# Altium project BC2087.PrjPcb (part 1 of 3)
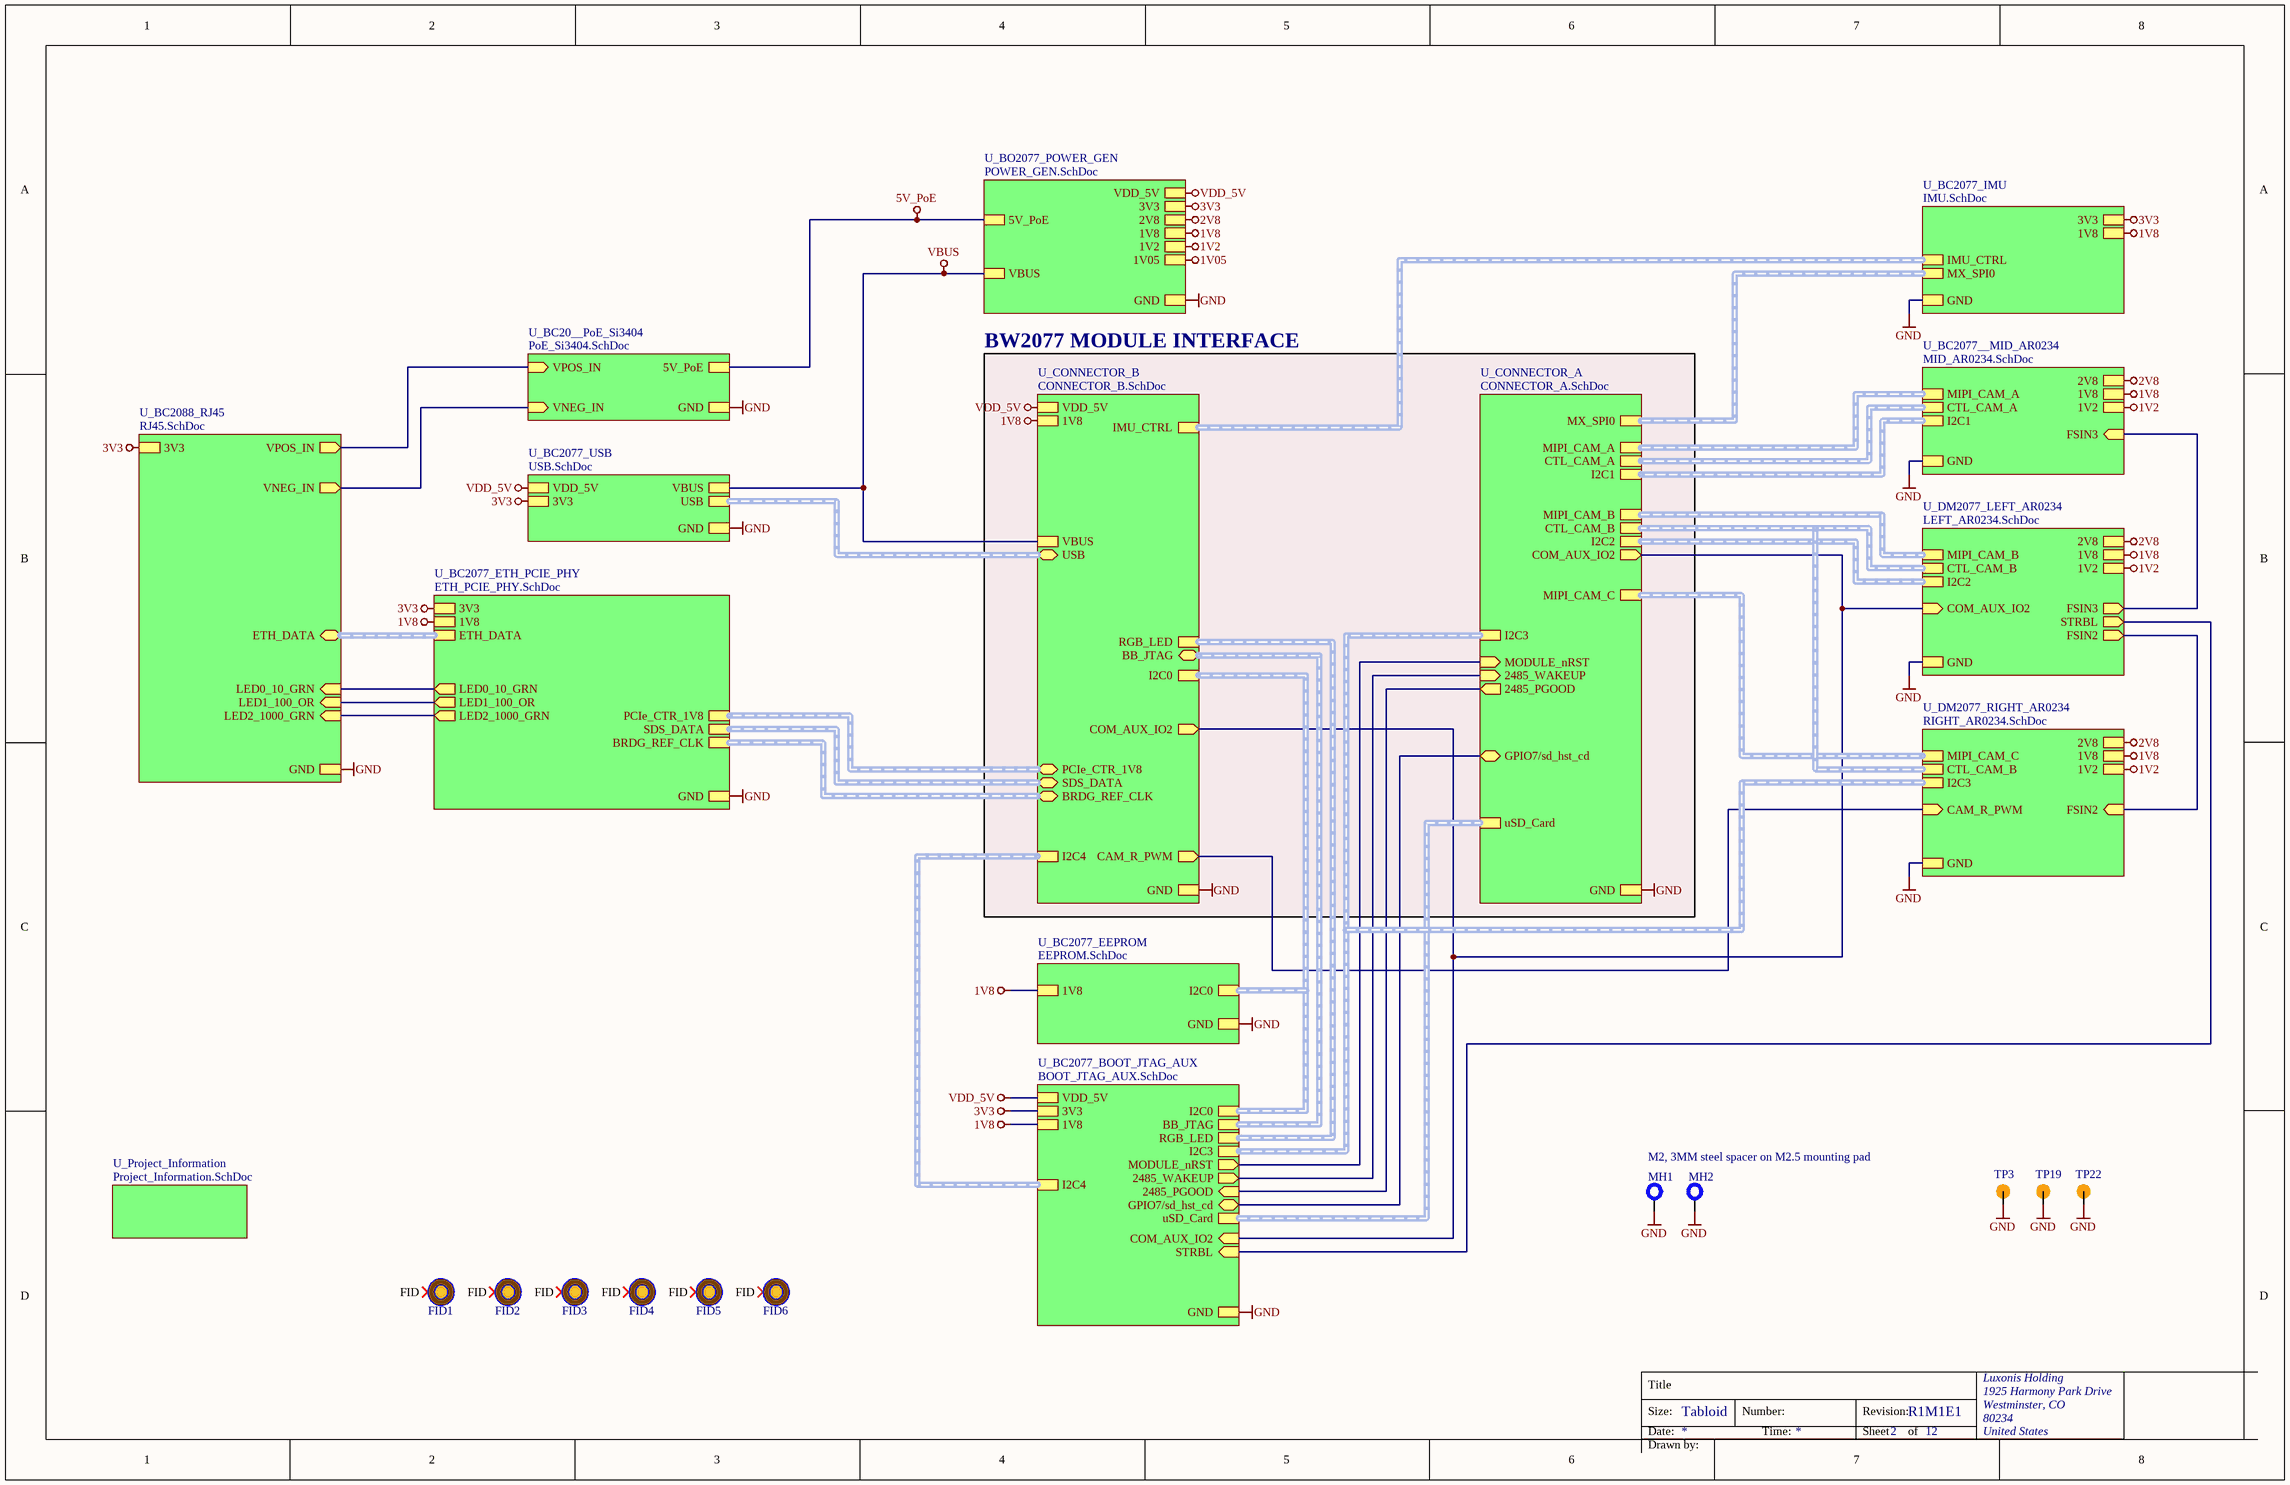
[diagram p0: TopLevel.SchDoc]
document_number: D2088000; drawn_by: Boris Chou / Blaz Kvas; project_title: BC2087; revision: R1M1E1
15 sheets, 302 parts. Net scope: strictly hierarchical (ports join the sheet entries above them; power ports are local).
Board file: BC2087.PcbDoc
Sheets:
  TopLevel.SchDoc
    U_Project_Information = Project_Information.SchDoc
    U_CONNECTOR_B = CONNECTOR_B.SchDoc
    U_CONNECTOR_A = CONNECTOR_A.SchDoc
    U_BC2077_ETH_PCIE_PHY = ETH_PCIE_PHY.SchDoc
    U_BC2088_RJ45 = RJ45.SchDoc
    U_BC2077_USB = USB.SchDoc
    U_BC2077_BOOT_JTAG_AUX = BOOT_JTAG_AUX.SchDoc
    U_BC20__PoE_Si3404 = PoE_Si3404.SchDoc
    U_BO2077_POWER_GEN = POWER_GEN.SchDoc
    U_BC2077__MID_AR0234 = MID_AR0234.SchDoc
    U_DM2077_RIGHT_AR0234 = RIGHT_AR0234.SchDoc
    U_DM2077_LEFT_AR0234 = LEFT_AR0234.SchDoc
    U_BC2077_IMU = IMU.SchDoc
    U_BC2077_EEPROM = EEPROM.SchDoc

## Sheet TopLevel.SchDoc: =project_title
size Tabloid; CompanyName: Luxonis Holding; DrawnBy: Boris Chou / Blaz Kvas; Organization: Luxonis Holding; Address1: 1925 Harmony Park Drive; Address2: Westminster, CO; Address3: 80234; Address4: United States; DocumentNumber: D2088000; Revision: R1M1E1; SheetNumber: 2; SheetTotal: 12

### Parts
FID1  FIDUCIAL_ROUND_1MM  [FIDUCIAL_ROUND_1MM]  (value not drawn)  (no BOM)
FID2  FIDUCIAL_ROUND_1MM  [FIDUCIAL_ROUND_1MM]  (value not drawn)  (no BOM)
FID3  FIDUCIAL_ROUND_1MM  [FIDUCIAL_ROUND_1MM]  (value not drawn)  (no BOM)
FID4  FIDUCIAL_ROUND_1MM  [FIDUCIAL_ROUND_1MM]  (value not drawn)  (no BOM)
FID5  FIDUCIAL_ROUND_1MM  [FIDUCIAL_ROUND_1MM]  (value not drawn)  (no BOM)
FID6  FIDUCIAL_ROUND_1MM  [FIDUCIAL_ROUND_1MM]  (value not drawn)  (no BOM)
MH1  M2, 3MM steel spacer on M2.5 mounting pad  [9774030243R]
MH2  M2, 3MM steel spacer on M2.5 mounting pad  [9774030243R]  (value not drawn)
TP3  TP100_200_NS  [TP100_200_NS]  (value not drawn)  (no BOM)
TP19  TP100_200_NS  [TP100_200_NS]  (value not drawn)  (no BOM)
TP22  TP100_200_NS  [TP100_200_NS]  (value not drawn)  (no BOM)

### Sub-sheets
U_BC20__PoE_Si3404 = PoE_Si3404.SchDoc: 5V_PoE, GND, VPOS_IN (in), VNEG_IN (in)
U_BC2077__MID_AR0234 = MID_AR0234.SchDoc: 2V8, 1V2, I2C1 (harness I2C1), MIPI_CAM_A (harness MIPI_CAM_A), CTL_CAM_A (harness CTL_CAM_A), GND, 1V8, FSIN3 (in)
U_BC2077_BOOT_JTAG_AUX = BOOT_JTAG_AUX.SchDoc: RGB_LED (harness BOOT), BB_JTAG (harness BB_JTAG), uSD_Card (harness uSD_Card), 2485_WAKEUP (out), I2C3 (harness I2C3), MODULE_nRST (out), 2485_PGOOD (in), 1V8, 3V3, GND, VDD_5V, I2C0 (harness I2C0), GPIO7/sd_hst_cd (bidir), STRBL (in), COM_AUX_IO2 (in), I2C4 (harness I2C4)
U_BC2077_EEPROM = EEPROM.SchDoc: 1V8, GND, I2C0 (harness I2C0)
U_BC2077_ETH_PCIE_PHY = ETH_PCIE_PHY.SchDoc: ETH_DATA (harness ETH_DATA), LED0_10_GRN (out), LED1_100_OR (out), LED2_1000_GRN (out), SDS_DATA (harness Harness), 3V3, GND, BRDG_REF_CLK (harness BRDG_REF_CLK), 1V8, PCIe_CTR_1V8 (harness PCIe_CTR_1V8)
U_BC2077_IMU = IMU.SchDoc: GND, 3V3, 1V8, MX_SPI0 (harness MX_SPI0), IMU_CTRL (harness IMU_CTRL)
U_BC2077_USB = USB.SchDoc: USB (harness USB), GND, 3V3, VBUS, VDD_5V
U_BC2088_RJ45 = RJ45.SchDoc: GND, LED0_10_GRN (in), 3V3, LED2_1000_GRN (in), LED1_100_OR (in), VPOS_IN (out), VNEG_IN (out), ETH_DATA (bidir, harness ETH_DATA)
U_BO2077_POWER_GEN = POWER_GEN.SchDoc: GND, 3V3, 1V8, 5V_PoE, VBUS, 1V2, 2V8, 1V05, VDD_5V
U_CONNECTOR_A = CONNECTOR_A.SchDoc: I2C2 (harness I2C2), I2C1 (harness I2C1), uSD_Card (harness uSD_Card), MIPI_CAM_C (harness MIPI_CAM_C), CTL_CAM_A (harness CTL_CAM_A), MIPI_CAM_A (harness MIPI_CAM_A), MIPI_CAM_B (harness MIPI_CAM_B), GND, I2C3 (harness I2C3), CTL_CAM_B (harness CTL_CAM_B), COM_AUX_IO2 (out), MODULE_nRST (in), 2485_WAKEUP (in), 2485_PGOOD (out), GPIO7/sd_hst_cd (bidir), MX_SPI0 (harness MX_SPI0)
U_CONNECTOR_B = CONNECTOR_B.SchDoc: VBUS, I2C0 (harness I2C0), VDD_5V, GND, PCIe_CTR_1V8 (bidir, harness PCIe_CTR_1V8), BB_JTAG (bidir, harness BB_JTAG), USB (bidir, harness USB), SDS_DATA (bidir, harness Harness), BRDG_REF_CLK (bidir, harness BRDG_REF_CLK), IMU_CTRL (harness IMU_CTRL), RGB_LED (harness BOOT), 1V8, CAM_R_PWM (out), I2C4, COM_AUX_IO2 (out)
U_DM2077_LEFT_AR0234 = LEFT_AR0234.SchDoc: I2C2 (harness I2C2), CTL_CAM_B (harness CTL_CAM_B), MIPI_CAM_B (harness MIPI_CAM_B), 1V2, 2V8, GND, 1V8, FSIN2 (out), COM_AUX_IO2 (in), FSIN3 (out), STRBL (out)
U_DM2077_RIGHT_AR0234 = RIGHT_AR0234.SchDoc: MIPI_CAM_C (harness MIPI_CAM_C), I2C3 (harness I2C2), 1V2, 2V8, GND, 1V8, FSIN2 (in), CTL_CAM_B (harness CTL_CAM_B), CAM_R_PWM (in)
U_Project_Information = Project_Information.SchDoc: no entries

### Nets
1V2: sheet U_BO2077_POWER_GEN/1V2, sheet U_BC2077__MID_AR0234/1V2, sheet U_DM2077_RIGHT_AR0234/1V2, sheet U_DM2077_LEFT_AR0234/1V2
1V8: sheet U_CONNECTOR_B/1V8, sheet U_BC2077_ETH_PCIE_PHY/1V8, sheet U_BC2077_BOOT_JTAG_AUX/1V8, sheet U_BO2077_POWER_GEN/1V8, sheet U_BC2077__MID_AR0234/1V8, sheet U_DM2077_RIGHT_AR0234/1V8, sheet U_DM2077_LEFT_AR0234/1V8, sheet U_BC2077_IMU/1V8, sheet U_BC2077_EEPROM/1V8
2V8: sheet U_BO2077_POWER_GEN/2V8, sheet U_BC2077__MID_AR0234/2V8, sheet U_DM2077_RIGHT_AR0234/2V8, sheet U_DM2077_LEFT_AR0234/2V8
3V3: sheet U_BC2077_ETH_PCIE_PHY/3V3, sheet U_BC2088_RJ45/3V3, sheet U_BC2077_USB/3V3, sheet U_BC2077_BOOT_JTAG_AUX/3V3, sheet U_BO2077_POWER_GEN/3V3, sheet U_BC2077_IMU/3V3
5V_PoE: sheet U_BC20__PoE_Si3404/5V_PoE, sheet U_BO2077_POWER_GEN/5V_PoE
GND: MH1.1 MH2.1 TP3.1 TP19.1 TP22.1 ; sheet U_CONNECTOR_B/GND, sheet U_CONNECTOR_A/GND, sheet U_BC2077_ETH_PCIE_PHY/GND, sheet U_BC2088_RJ45/GND, sheet U_BC2077_USB/GND, sheet U_BC2077_BOOT_JTAG_AUX/GND, sheet U_BC20__PoE_Si3404/GND, sheet U_BO2077_POWER_GEN/GND, sheet U_BC2077__MID_AR0234/GND, sheet U_DM2077_RIGHT_AR0234/GND, sheet U_DM2077_LEFT_AR0234/GND, sheet U_BC2077_IMU/GND, sheet U_BC2077_EEPROM/GND
VBUS: sheet U_CONNECTOR_B/VBUS, sheet U_BC2077_USB/VBUS, sheet U_BO2077_POWER_GEN/VBUS
VDD_5V: sheet U_CONNECTOR_B/VDD_5V, sheet U_BC2077_USB/VDD_5V, sheet U_BC2077_BOOT_JTAG_AUX/VDD_5V, sheet U_BO2077_POWER_GEN/VDD_5V
VNEG_IN: sheet U_BC2088_RJ45/VNEG_IN, sheet U_BC20__PoE_Si3404/VNEG_IN
2485_PGOOD: sheet U_CONNECTOR_A/2485_PGOOD, sheet U_BC2077_BOOT_JTAG_AUX/2485_PGOOD
2485_WAKEUP: sheet U_CONNECTOR_A/2485_WAKEUP, sheet U_BC2077_BOOT_JTAG_AUX/2485_WAKEUP
CAM_R_PWM: sheet U_CONNECTOR_B/CAM_R_PWM, sheet U_DM2077_RIGHT_AR0234/CAM_R_PWM
COM_AUX_IO2: sheet U_CONNECTOR_B/COM_AUX_IO2, sheet U_CONNECTOR_A/COM_AUX_IO2, sheet U_BC2077_BOOT_JTAG_AUX/COM_AUX_IO2, sheet U_DM2077_LEFT_AR0234/COM_AUX_IO2
FSIN2: sheet U_DM2077_RIGHT_AR0234/FSIN2, sheet U_DM2077_LEFT_AR0234/FSIN2
FSIN3: sheet U_BC2077__MID_AR0234/FSIN3, sheet U_DM2077_LEFT_AR0234/FSIN3
GPIO7/sd_hst_cd: sheet U_CONNECTOR_A/GPIO7/sd_hst_cd, sheet U_BC2077_BOOT_JTAG_AUX/GPIO7/sd_hst_cd
LED0_10_GRN: sheet U_BC2077_ETH_PCIE_PHY/LED0_10_GRN, sheet U_BC2088_RJ45/LED0_10_GRN
LED1_100_OR: sheet U_BC2077_ETH_PCIE_PHY/LED1_100_OR, sheet U_BC2088_RJ45/LED1_100_OR
LED2_1000_GRN: sheet U_BC2077_ETH_PCIE_PHY/LED2_1000_GRN, sheet U_BC2088_RJ45/LED2_1000_GRN
MODULE_nRST: sheet U_CONNECTOR_A/MODULE_nRST, sheet U_BC2077_BOOT_JTAG_AUX/MODULE_nRST
STRBL: sheet U_BC2077_BOOT_JTAG_AUX/STRBL, sheet U_DM2077_LEFT_AR0234/STRBL
VPOS_IN: sheet U_BC2088_RJ45/VPOS_IN, sheet U_BC20__PoE_Si3404/VPOS_IN

Not connected (* = marked no-connect by the designer): FID1 FID*; FID2 FID*; FID3 FID*; FID4 FID*; FID5 FID*; FID6 FID*

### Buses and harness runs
harness sheet U_BC2077__MID_AR0234/CTL_CAM_A = sheet U_CONNECTOR_A/CTL_CAM_A
harness sheet U_BC2077__MID_AR0234/I2C1 = sheet U_CONNECTOR_A/I2C1
harness sheet U_BC2077__MID_AR0234/MIPI_CAM_A = sheet U_CONNECTOR_A/MIPI_CAM_A
harness sheet U_BC2077_BOOT_JTAG_AUX/BB_JTAG = sheet U_CONNECTOR_B/BB_JTAG
harness sheet U_BC2077_BOOT_JTAG_AUX/I2C0 = sheet U_BC2077_EEPROM/I2C0 = sheet U_CONNECTOR_B/I2C0
harness sheet U_BC2077_BOOT_JTAG_AUX/I2C3 = sheet U_CONNECTOR_A/I2C3 = sheet U_DM2077_RIGHT_AR0234/I2C3
harness sheet U_BC2077_BOOT_JTAG_AUX/I2C4 = sheet U_CONNECTOR_B/I2C4
harness sheet U_BC2077_BOOT_JTAG_AUX/RGB_LED = sheet U_CONNECTOR_B/RGB_LED
harness sheet U_BC2077_BOOT_JTAG_AUX/uSD_Card = sheet U_CONNECTOR_A/uSD_Card
harness sheet U_BC2077_ETH_PCIE_PHY/BRDG_REF_CLK = sheet U_CONNECTOR_B/BRDG_REF_CLK
harness sheet U_BC2077_ETH_PCIE_PHY/ETH_DATA = sheet U_BC2088_RJ45/ETH_DATA
harness sheet U_BC2077_ETH_PCIE_PHY/PCIe_CTR_1V8 = sheet U_CONNECTOR_B/PCIe_CTR_1V8
harness sheet U_BC2077_ETH_PCIE_PHY/SDS_DATA = sheet U_CONNECTOR_B/SDS_DATA
harness sheet U_BC2077_IMU/IMU_CTRL = sheet U_CONNECTOR_B/IMU_CTRL
harness sheet U_BC2077_IMU/MX_SPI0 = sheet U_CONNECTOR_A/MX_SPI0
harness sheet U_BC2077_USB/USB = sheet U_CONNECTOR_B/USB
harness sheet U_CONNECTOR_A/CTL_CAM_B = sheet U_DM2077_LEFT_AR0234/CTL_CAM_B = sheet U_DM2077_RIGHT_AR0234/CTL_CAM_B
harness sheet U_CONNECTOR_A/I2C2 = sheet U_DM2077_LEFT_AR0234/I2C2
harness sheet U_CONNECTOR_A/MIPI_CAM_B = sheet U_DM2077_LEFT_AR0234/MIPI_CAM_B
harness sheet U_CONNECTOR_A/MIPI_CAM_C = sheet U_DM2077_RIGHT_AR0234/MIPI_CAM_C

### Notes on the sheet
- BW2077 MODULE INTERFACE

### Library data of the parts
FID1-FID6 = FIDUCIAL: Fiducial with various available footprints
MH1 MH2 = 9774030243R: MP ROUND STANDOFF M2X0.4 STEEL 3MM; Manufacturer 1: Wurth Electronics; Plating: Tin; Threaded/Unthreaded: Threaded; Outside Diameter: 0.171inch
TP3 TP19 TP22 = TEST_POINT

## Sheet Project_Information.SchDoc: =project_title
size Tabloid; CompanyName: Luxonis Holding; DrawnBy: Boris Chou / Blaz Kvas; Organization: Luxonis Holding; Address1: 1925 Harmony Park Drive; Address2: Westminster, CO; Address3: 80234; Address4: United States; DocumentNumber: D2088000; Revision: R1M1E1; SheetNumber: 1; SheetTotal: 12
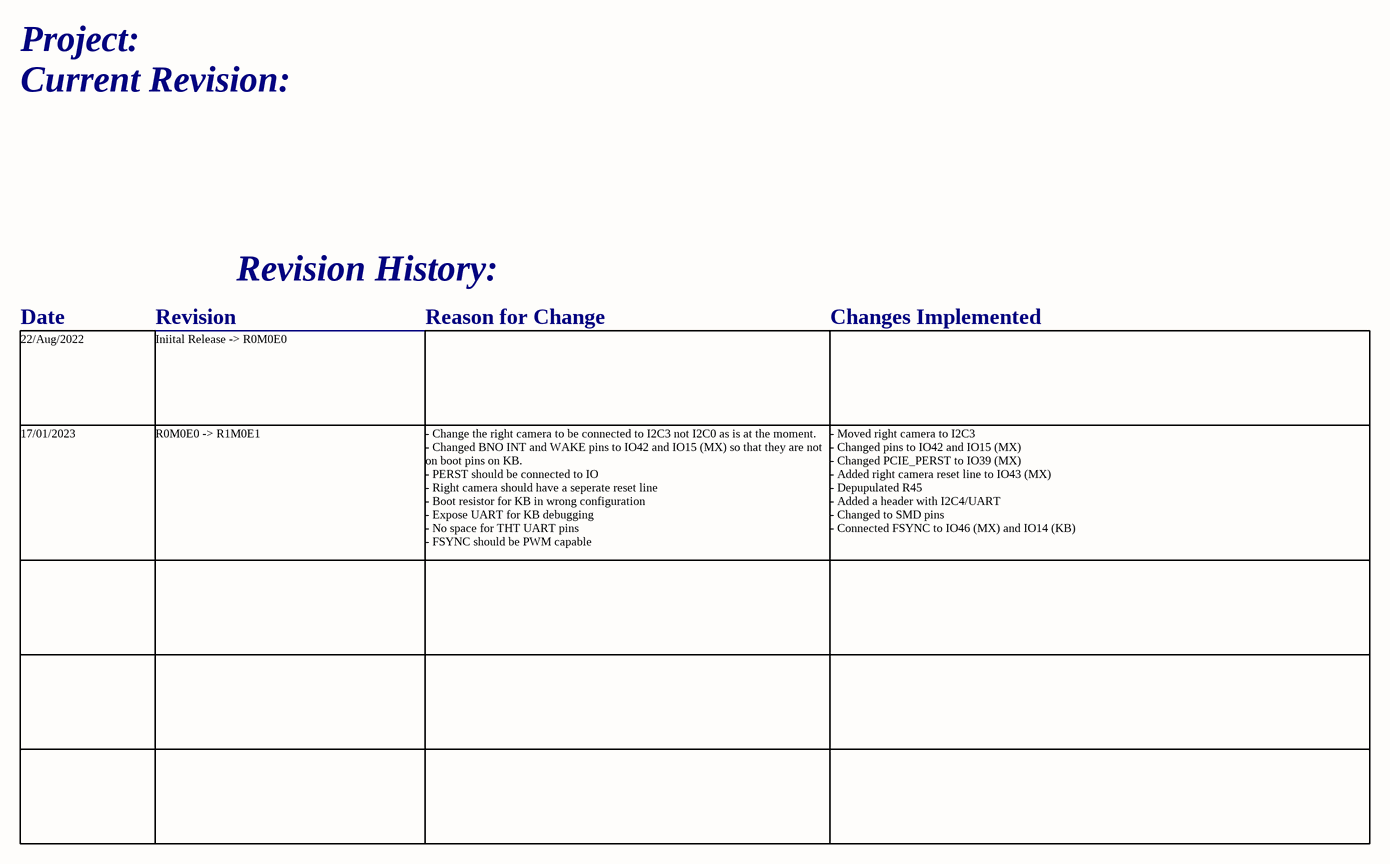
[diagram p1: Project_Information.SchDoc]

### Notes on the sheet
- Project:
- Current Revision:
- Revision History:
- Date
- Revision
- Reason for Change
- Changes Implemented
- 22/Aug/2022
- Iniital Release -> R0M0E0
- 17/01/2023
- R0M0E0 -> R1M0E1
- - Change the right camera to be connected to I2C3 not I2C0 as is at the moment.
  - Changed BNO INT and WAKE pins to IO42 and IO15 (MX) so that they are not on boot pins on KB.
  - PERST should be connected to IO
  - Right camera should have a seperate reset line
  - Boot resistor for KB in wrong configuration
  - Expose UART for KB debugging
  - No space for THT UART pins
  - FSYNC should be PWM capable
- - Moved right camera to I2C3
  - Changed pins to IO42 and IO15 (MX)
  - Changed PCIE_PERST to IO39 (MX)
  - Added right camera reset line to IO43 (MX)
  - Depupulated R45
  - Added a header with I2C4/UART
  - Changed to SMD pins
  - Connected FSYNC to IO46 (MX) and IO14 (KB)

## Sheet CONNECTOR_B.SchDoc: =project_title
size Tabloid; CompanyName: Luxonis Holding; DrawnBy: Boris Chou / Blaz Kvas; Organization: Luxonis Holding; Address1: 1925 Harmony Park Drive; Address2: Westminster, CO; Address3: 80234; Address4: United States; DocumentNumber: D2088000; Revision: R1M1E1; SheetNumber: 6; SheetTotal: 12
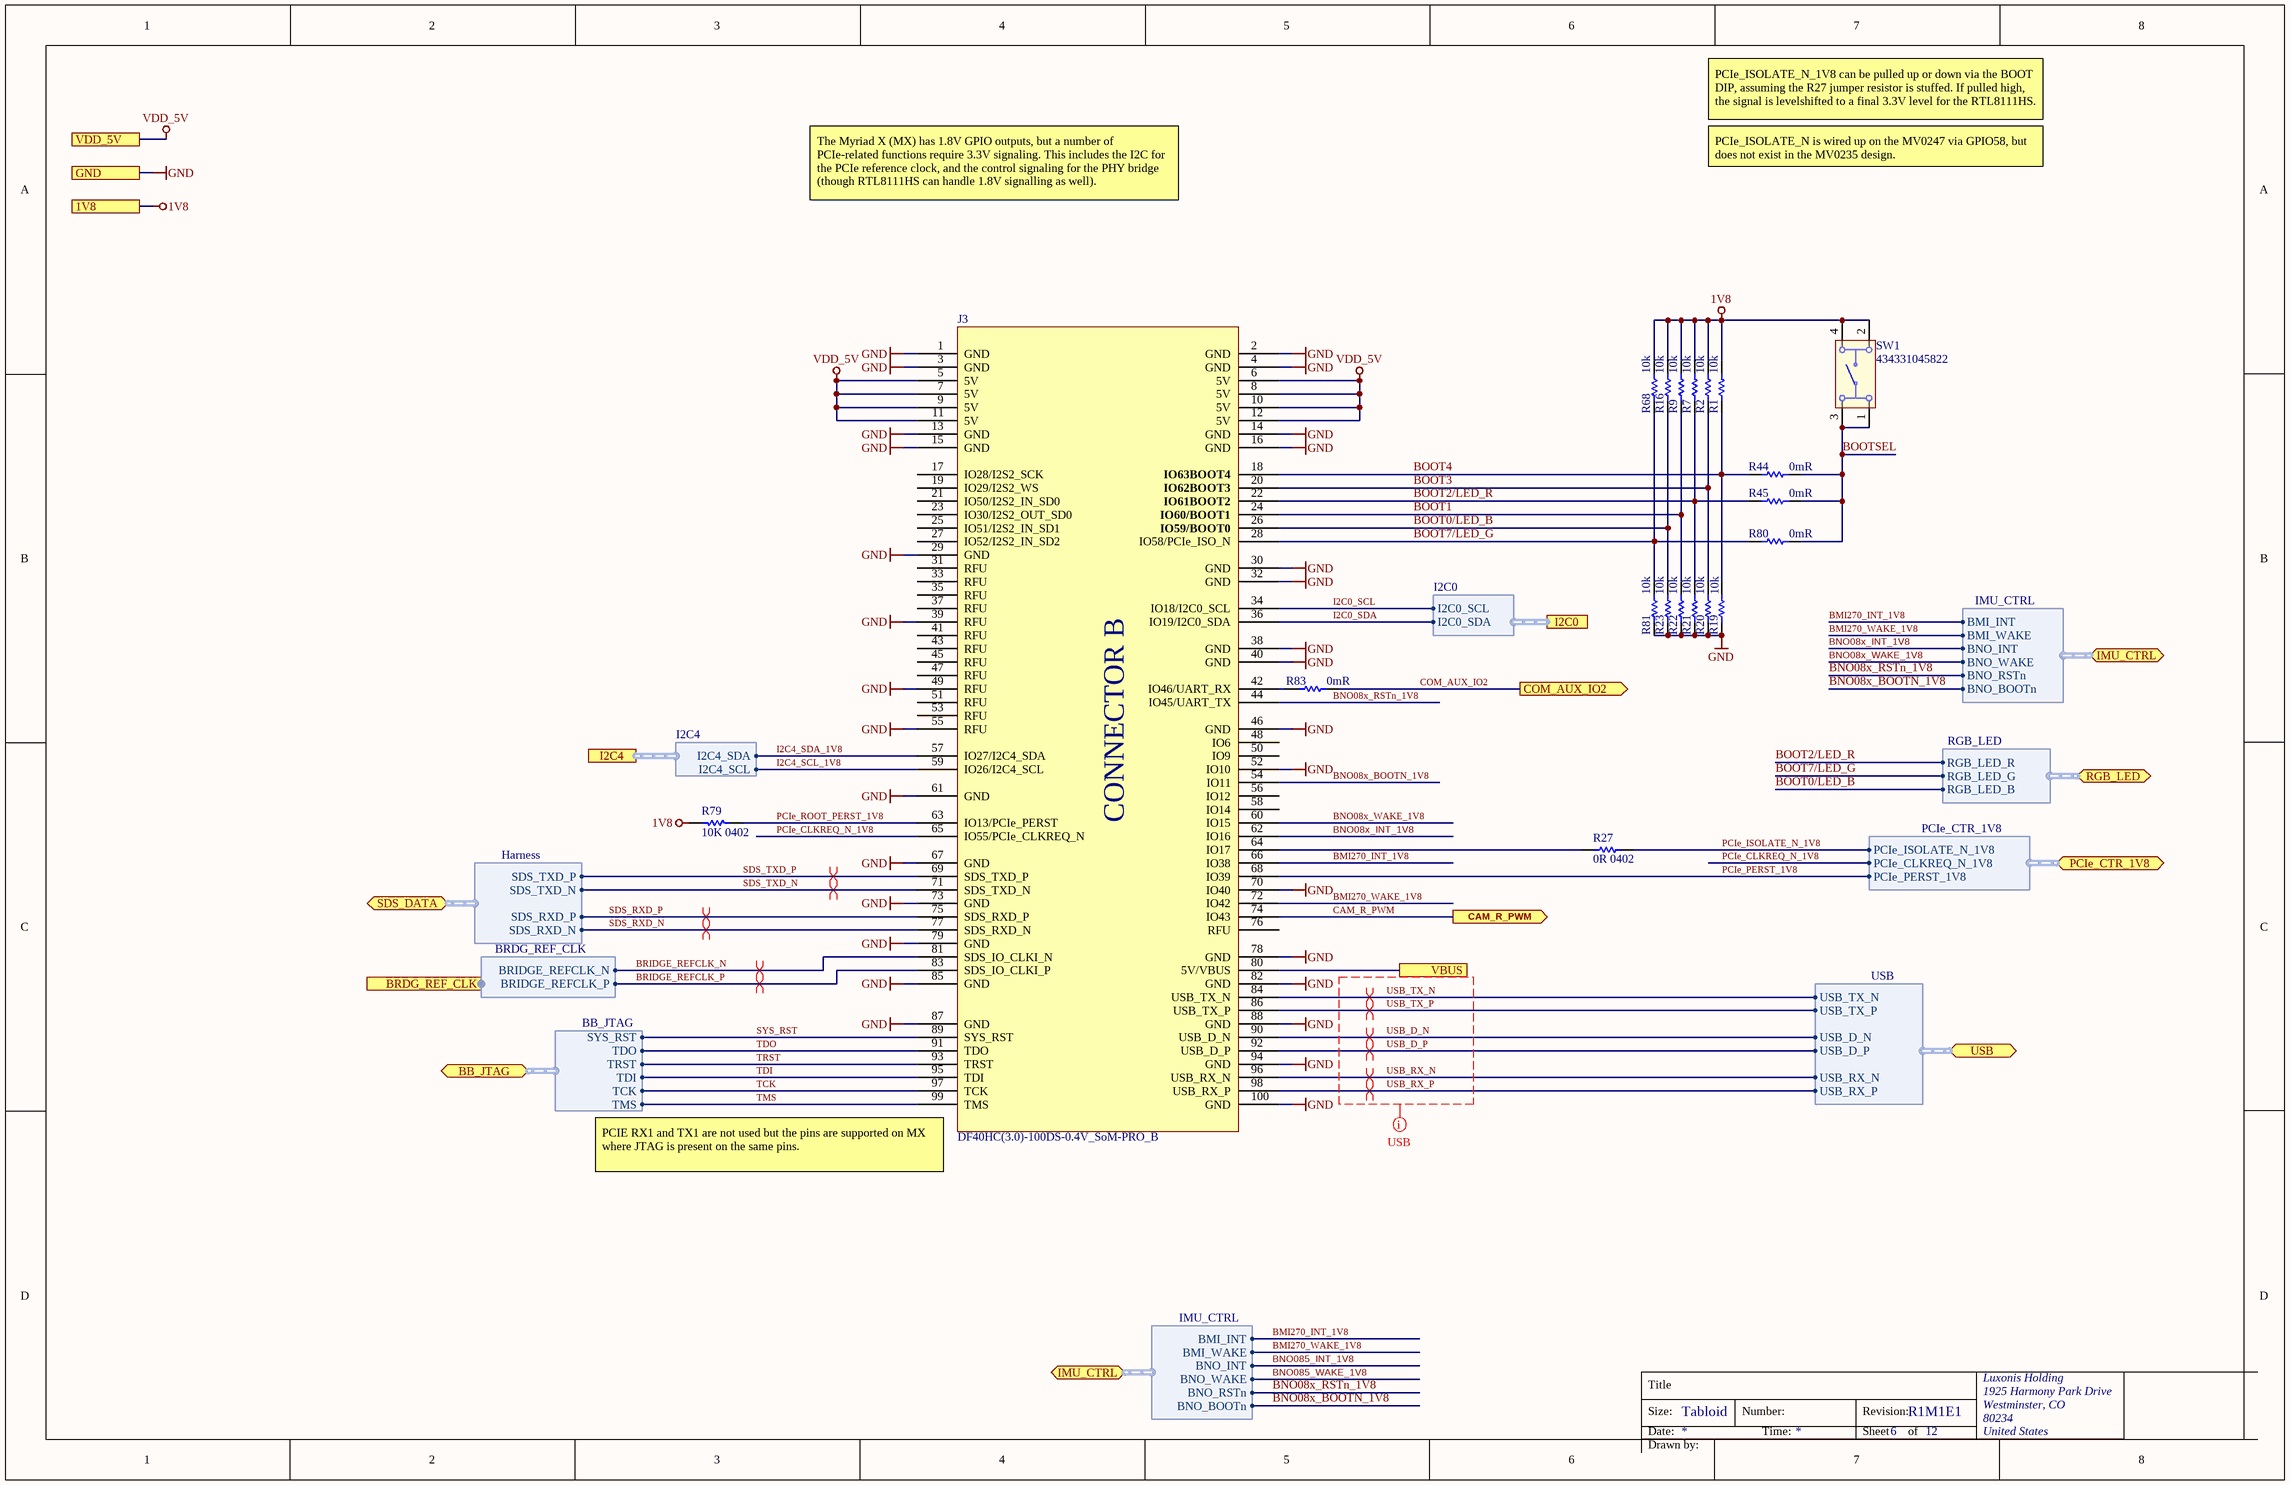
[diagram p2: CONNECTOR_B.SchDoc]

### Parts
J3  DF40HC(3.0)-100DS-0.4V_SoM-PRO_B  [CON_B_BW2099_SoM_DF40HC-3.0-100DS-0.4V_minpad]
R1  Resistance: 10k  [RESC0402(1005)_L]  (hidden comment: RC0402FR-1310KL)
R2  Resistance: 10k  [RESC0402(1005)_L]  (hidden comment: RC0402FR-1310KL)
R7  Resistance: 10k  [RESC0402(1005)_L]  (hidden comment: RC0402FR-1310KL)
R9  Resistance: 10k  [RESC0402(1005)_L]  (hidden comment: RC0402FR-1310KL)
R16  Resistance: 10k  [RESC0402(1005)_L]  (hidden comment: RC0402FR-1310KL)
R19  Resistance: 10k  [RESC0402(1005)_L]  (hidden comment: RC0402FR-1310KL)
R20  Resistance: 10k  [RESC0402(1005)_L]  (hidden comment: RC0402FR-1310KL)
R21  Resistance: 10k  [RESC0402(1005)_L]  (hidden comment: RC0402FR-1310KL)
R22  Resistance: 10k  [RESC0402(1005)_L]  (hidden comment: RC0402FR-1310KL)
R23  Resistance: 10k  [RESC0402(1005)_L]  (hidden comment: RC0402FR-1310KL)
R27  0R 0402  [RESC0402(1005)_L]
R44  Resistance: 0mR  [RESC0402(1005)_L]  (hidden comment: CRCW04020000Z0ED)
R45  Resistance: 0mR  [RESC0402(1005)_L]  (hidden comment: CRCW04020000Z0ED)
R68  Resistance: 10k  [RESC0402(1005)_L]  (hidden comment: RC0402FR-1310KL)
R79  10K 0402  [RESC0402(1005)_N]
R80  Resistance: 0mR  [RESC0402(1005)_L]  (hidden comment: CRCW04020000Z0ED)
R81  Resistance: 10k  [RESC0402(1005)_L]  (hidden comment: RC0402FR-1310KL)
R83  Resistance: 0mR  [RESC0402(1005)_L]  (hidden comment: CRCW04020000Z0ED)
SW1  434331045822  [434331045822]

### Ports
1V8, BB_JTAG (bidir, harness BB_JTAG), BRDG_REF_CLK (harness BRDG_REF_CLK), CAM_R_PWM (out), COM_AUX_IO2 (out), GND, I2C0 (harness I2C0), I2C4 (harness I2C4), IMU_CTRL (bidir, harness IMU_CTRL), PCIe_CTR_1V8 (bidir, harness PCIe_CTR_1V8), RGB_LED (bidir, harness RGB_LED), SDS_DATA (bidir, harness Harness), USB (bidir, harness USB), VBUS, VDD_5V

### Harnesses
USB: USB_RX_P, USB_RX_N, USB_D_P, USB_D_N, USB_TX_P, USB_TX_N
I2C0: I2C0_SDA, I2C0_SCL
BB_JTAG: SYS_RST, TDO, TRST, TDI, TCK, TMS
Harness: SDS_TXD_P, SDS_TXD_N, SDS_RXD_P, SDS_RXD_N
PCIe_CTR_1V8: PCIe_CLKREQ_N_1V8, PCIe_ISOLATE_N_1V8, PCIe_PERST_1V8
BRDG_REF_CLK: BRIDGE_REFCLK_P, BRIDGE_REFCLK_N
RGB_LED: RGB_LED_G, RGB_LED_B, RGB_LED_R
IMU_CTRL: BMI_INT, BMI_WAKE, BNO_INT, BNO_WAKE, BNO_RSTn, BNO_BOOTn
I2C4: I2C4_SDA, I2C4_SCL

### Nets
1V8: R1.2 R2.2 R7.2 R9.2 R16.2 R68.2 R79.1 SW1.2 SW1.4 ; port 1V8
GND: J3.1(GND) J3.2(GND) J3.3(GND) J3.4(GND) J3.13(GND) J3.14(GND) J3.15(GND) J3.16(GND) J3.29(GND) J3.30(GND) J3.32(GND) J3.38(GND) J3.39(RFU) J3.40(GND) J3.46(GND) J3.49(RFU) J3.52(IO10) J3.55(RFU) J3.61(GND) J3.67(GND) J3.70(IO40) J3.73(GND) J3.78(GND) J3.79(GND) J3.82(GND) J3.85(GND) J3.87(GND) J3.88(GND) J3.94(GND) J3.100(GND) R19.1 R20.1 R21.1 R22.1 R23.1 R81.1 ; port GND
VBUS: J3.80(5V/VBUS) ; port VBUS
VDD_5V: J3.5(5V) J3.6(5V) J3.7(5V) J3.8(5V) J3.9(5V) J3.10(5V) J3.11(5V) J3.12(5V) ; port VDD_5V
BMI270_INT_1V8: J3.66(IO38) ; port IMU_CTRL.BMI_INT
BMI270_WAKE_1V8: J3.72(IO42) ; port IMU_CTRL.BMI_WAKE
BNO08x_BOOTN_1V8: J3.54(IO11) ; port IMU_CTRL.BNO_BOOTn
BNO08x_RSTn_1V8: J3.44(IO45/UART_TX) ; port IMU_CTRL.BNO_RSTn
BNO085_INT_1V8: J3.62(IO16) ; port IMU_CTRL.BNO_INT  [also labelled BNO08x_INT_1V8]
BNO085_WAKE_1V8: J3.60(IO15) ; port IMU_CTRL.BNO_WAKE  [also labelled BNO08x_WAKE_1V8]
BOOT0/LED_B: J3.26(IO59/BOOT0) R16.1 R23.2 ; port RGB_LED.RGB_LED_B
BOOT1: J3.24(IO60/BOOT1) R9.1 R22.2
BOOT2/LED_R: J3.22(IO61BOOT2) R7.1 R21.2 R45.2 ; port RGB_LED.RGB_LED_R
BOOT3: J3.20(IO62BOOT3) R2.1 R20.2
BOOT4: J3.18(IO63BOOT4) R1.1 R19.2 R44.2
BOOT7/LED_G: J3.28(IO58/PCIe_ISO_N) R68.1 R80.2 R81.2 ; port RGB_LED.RGB_LED_G
BOOTSEL: R44.1 R45.1 R80.1 SW1.1 SW1.3
BRIDGE_REFCLK_N: J3.81(SDS_IO_CLKI_N) ; port BRDG_REF_CLK.BRIDGE_REFCLK_N
BRIDGE_REFCLK_P: J3.83(SDS_IO_CLKI_P) ; port BRDG_REF_CLK.BRIDGE_REFCLK_P
CAM_R_PWM: J3.74(IO43) ; port CAM_R_PWM
COM_AUX_IO2: R83.1 ; port COM_AUX_IO2
I2C0_SCL: J3.34(IO18/I2C0_SCL) ; port I2C0.I2C0_SCL
I2C0_SDA: J3.36(IO19/I2C0_SDA) ; port I2C0.I2C0_SDA
I2C4_SCL_1V8: J3.59(IO26/I2C4_SCL) ; port I2C4.I2C4_SCL
I2C4_SDA_1V8: J3.57(IO27/I2C4_SDA) ; port I2C4.I2C4_SDA
PCIe_CLKREQ_N_1V8: J3.65(IO55/PCIe_CLKREQ_N) ; port PCIe_CTR_1V8.PCIe_CLKREQ_N_1V8
PCIe_ISOLATE_N_1V8: R27.2 ; port PCIe_CTR_1V8.PCIe_ISOLATE_N_1V8
PCIe_PERST_1V8: J3.68(IO39) ; port PCIe_CTR_1V8.PCIe_PERST_1V8
PCIe_ROOT_PERST_1V8: J3.63(IO13/PCIe_PERST) R79.2
SDS_RXD_N: J3.77(SDS_RXD_N) ; port SDS_DATA.SDS_RXD_N
SDS_RXD_P: J3.75(SDS_RXD_P) ; port SDS_DATA.SDS_RXD_P
SDS_TXD_N: J3.71(SDS_TXD_N) ; port SDS_DATA.SDS_TXD_N
SDS_TXD_P: J3.69(SDS_TXD_P) ; port SDS_DATA.SDS_TXD_P
SYS_RST: J3.89(SYS_RST) ; port BB_JTAG.SYS_RST
TCK: J3.97(TCK) ; port BB_JTAG.TCK
TDI: J3.95(TDI) ; port BB_JTAG.TDI
TDO: J3.91(TDO) ; port BB_JTAG.TDO
TMS: J3.99(TMS) ; port BB_JTAG.TMS
TRST: J3.93(TRST) ; port BB_JTAG.TRST
USB_D_N: J3.90(USB_D_N) ; port USB.USB_D_N
USB_D_P: J3.92(USB_D_P) ; port USB.USB_D_P
USB_RX_N: J3.96(USB_RX_N) ; port USB.USB_RX_N
USB_RX_P: J3.98(USB_RX_P) ; port USB.USB_RX_P
USB_TX_N: J3.84(USB_TX_N) ; port USB.USB_TX_N
USB_TX_P: J3.86(USB_TX_P) ; port USB.USB_TX_P
NetJ3_42: J3.42(IO46/UART_RX) R83.2
NetJ3_64: J3.64(IO17) R27.1

Not connected (* = marked no-connect by the designer): J3 17(IO28/I2S2_SCK) 19(IO29/I2S2_WS) 21(IO50/I2S2_IN_SD0) 23(IO30/I2S2_OUT_SD0) 25(IO51/I2S2_IN_SD1) 27(IO52/I2S2_IN_SD2) 31(RFU) 33(RFU) 35(RFU) 37(RFU) 41(RFU) 43(RFU) 45(RFU) 47(RFU) 48(IO6) 50(IO9) 51(RFU) 53(RFU) 56(IO12) 58(IO14) 76(RFU)

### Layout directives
net class USB: USB_D_N, USB_D_P, USB_RX_N, USB_RX_P, USB_TX_N, USB_TX_P
differential pair; differential pair class 100ohm: BRIDGE_REFCLK_N, BRIDGE_REFCLK_P, SDS_RXD_N, SDS_RXD_P, SDS_TXD_N, SDS_TXD_P
differential pair; differential pair class USB3: USB_D_N, USB_D_P, USB_RX_N, USB_RX_P, USB_TX_N, USB_TX_P

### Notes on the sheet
- PCIe_ISOLATE_N_1V8 can be pulled up or down via the BOOT DIP, assuming the R27 jumper resistor is stuffed. If pulled high, the signal is levelshifted to a final 3.3V level for the RTL8111HS.
- PCIe_ISOLATE_N is wired up on the MV0247 via GPIO58, but does not exist in the MV0235 design.
- The Myriad X (MX) has 1.8V GPIO outputs, but a number of PCIe-related functions require 3.3V signaling. This includes the I2C for the PCIe reference clock, and the control signaling for the PHY bridge (though RTL8111HS can handle 1.8V signalling as well).
- (near J3) PCIE RX1 and TX1 are not used but the pins are supported on MX where JTAG is present on the same pins.

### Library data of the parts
J3 = CMP-005-000053-4: OAK-SoM-Pro base board conn. B; Manufacturer Part Number 1: DF40HC(3.0)-100DS-0.4V(58); Manufacturer 1: Hirose; Connector Type: Receptacle; Pitch: 0.016inch; Number of Positions: 100; System: Connector
R1 R2 R7 R9 R16 R19-R23 R68 R81 = CMP-013-000018-2: RES SMD 10K OHM 1% 0402 1/16W Chip Resistor, 0402 [1005 Metric], 10 kohm, RC Series, 50 V, Thick Film, 62.5 mW; Manufacturer 1: Yageo; Temperature Coefficient: 100ppm/°C; Power Rating: 62.5mW; Voltage Rating: 50V
R27 = CRCW04020000Z0ED: RES SMD 0 OHM JUMPER 1/16W 0402; Manufacturer 1: Vishay; Resistance: 0mR; Power Rating: 63mW; Voltage Rating: 50V; Temperature Coefficient: 100ppm/°C; Tolerance: 5%
R44 R45 R80 R83 = CMP-013-000022-2: RES SMD 0 OHM JUMPER 1/16W 0402; Manufacturer 1: Vishay; Power Rating: 63mW; Voltage Rating: 50V; Temperature Coefficient: 100ppm/°C; Tolerance: 5%; Value: 0R
R79 = RC0402FR-1310KL: RES SMD 10K OHM 1% 0402 1/16W Chip Resistor, 0402 [1005 Metric], 10 kohm, RC Series, 50 V, Thick Film, 62.5 mW; Manufacturer 1: Yageo; Resistance: 10kR; Temperature Coefficient: 100ppm/°C; Power Rating: 62.5mW; Voltage Rating: 50V
SW1 = CMP-011-00016-3: Keypad Switch, 1 Switches, SPST, Momentary-tactile, 0.05A, 12VDC, 2.65N, Solder Terminal, Surface Mount-right Angle; Manufacturer 1: Wurth Electronics; Voltage Rating: 12V; Max Current Rating: 50mA; Throw Configuration: SPST-NO

## Sheet CONNECTOR_A.SchDoc: =project_title
size Tabloid; CompanyName: Luxonis Holding; DrawnBy: Boris Chou / Blaz Kvas; Organization: Luxonis Holding; Address1: 1925 Harmony Park Drive; Address2: Westminster, CO; Address3: 80234; Address4: United States; DocumentNumber: D2088000; Revision: R1M1E1; SheetNumber: 5; SheetTotal: 12
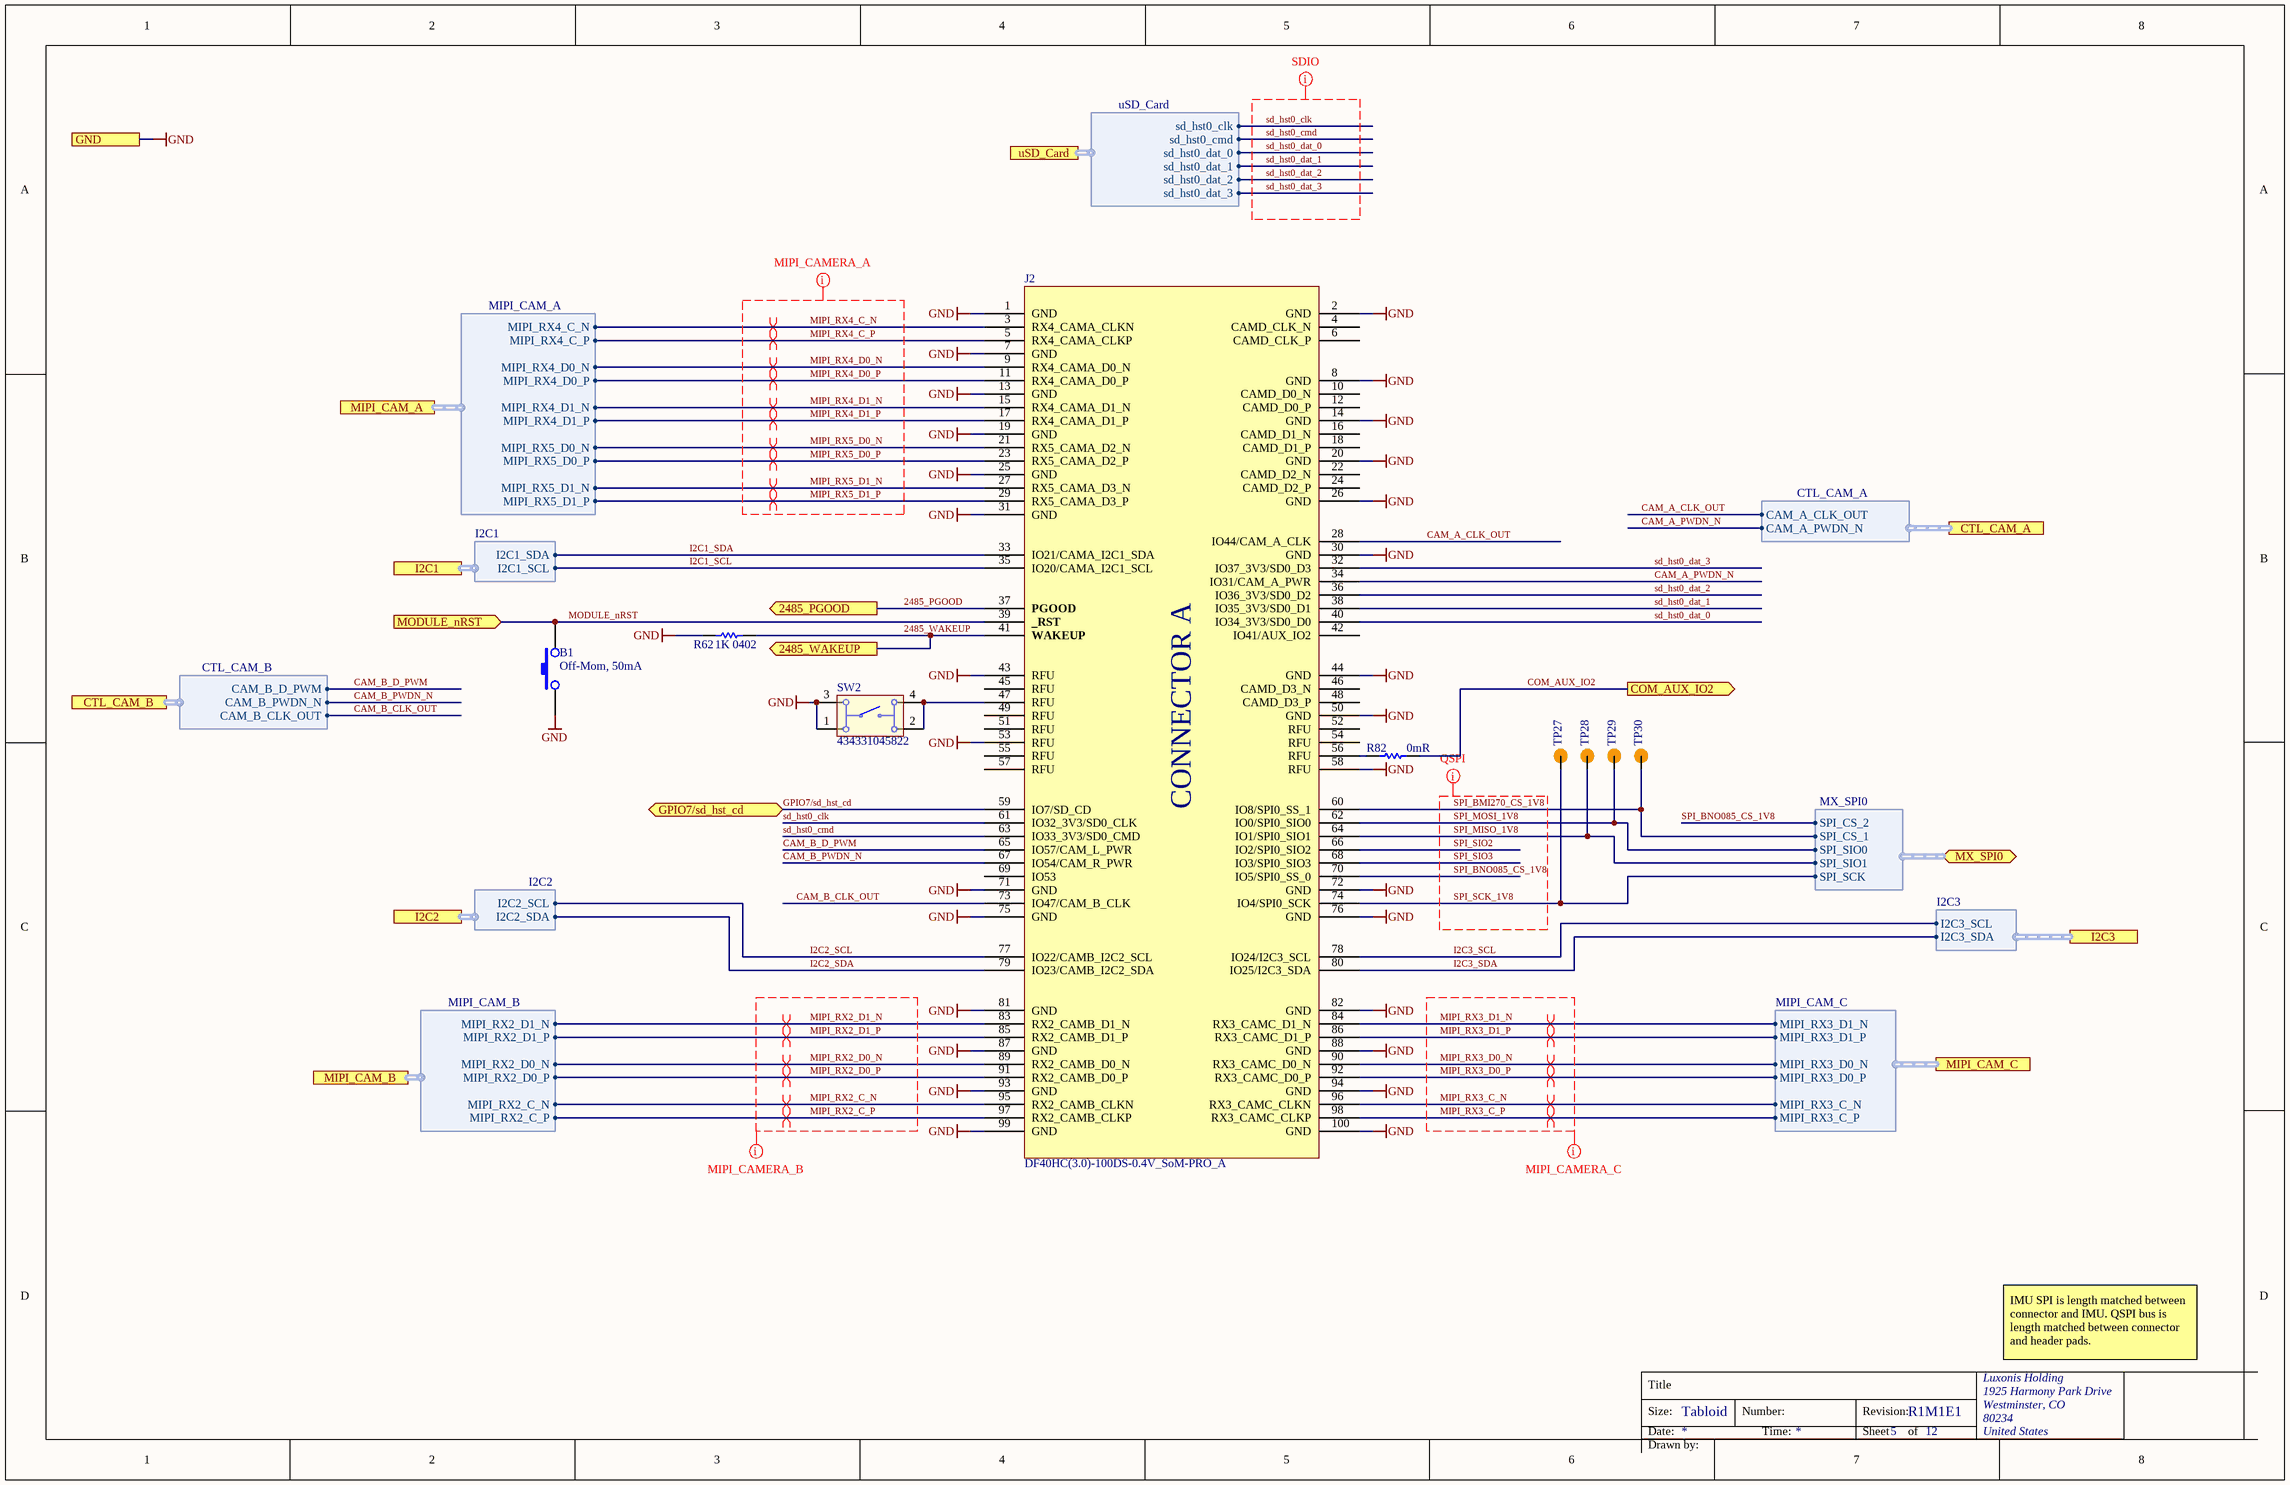
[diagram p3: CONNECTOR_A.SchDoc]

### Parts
B1  Off-Mom, 50mA  [DTSM-32N-V]
J2  DF40HC(3.0)-100DS-0.4V_SoM-PRO_A  [CON_A_BW2099_SoM_DF40HC-3.0-100DS-0.4V_minpad]
R62  1K 0402  [RESC0402(1005)_L]
R82  Resistance: 0mR  [RESC0402(1005)_L]  (hidden comment: CRCW04020000Z0ED)
SW2  434331045822  [434331045822]
TP27  TP100_200_NS  [TP100_200_NS]  (value not drawn)  (no BOM)
TP28  TP100_200_NS  [TP100_200_NS]  (value not drawn)  (no BOM)
TP29  TP100_200_NS  [TP100_200_NS]  (value not drawn)  (no BOM)
TP30  TP100_200_NS  [TP100_200_NS]  (value not drawn)  (no BOM)

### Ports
2485_PGOOD (out), 2485_WAKEUP (out), COM_AUX_IO2 (out), CTL_CAM_A (harness CTL_CAM_A), CTL_CAM_B (harness CTL_CAM_B), GND, GPIO7/sd_hst_cd (bidir), I2C1 (harness I2C1), I2C2 (harness I2C2), I2C3 (harness I2C3), MIPI_CAM_A (harness MIPI_CAM_A), MIPI_CAM_B (harness MIPI_CAM_B), MIPI_CAM_C (harness MIPI_CAM_C), MODULE_nRST (in), MX_SPI0 (bidir, harness MX_SPI0), uSD_Card (harness uSD_Card)

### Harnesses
MIPI_CAM_B: MIPI_RX2_C_P, MIPI_RX2_C_N, MIPI_RX2_D0_P, MIPI_RX2_D0_N, MIPI_RX2_D1_P, MIPI_RX2_D1_N
MIPI_CAM_A: MIPI_RX4_C_N, MIPI_RX4_C_P, MIPI_RX4_D0_N, MIPI_RX4_D0_P, MIPI_RX4_D1_N, MIPI_RX4_D1_P, MIPI_RX5_D0_N, MIPI_RX5_D0_P, MIPI_RX5_D1_N, MIPI_RX5_D1_P
MIPI_CAM_C: MIPI_RX3_C_P, MIPI_RX3_C_N, MIPI_RX3_D0_P, MIPI_RX3_D0_N, MIPI_RX3_D1_P, MIPI_RX3_D1_N
I2C2: I2C2_SDA, I2C2_SCL
I2C1: I2C1_SDA, I2C1_SCL
CTL_CAM_B: CAM_B_PWDN_N, CAM_B_D_PWM, CAM_B_CLK_OUT
I2C3: I2C3_SDA, I2C3_SCL
CTL_CAM_A: CAM_A_PWDN_N, CAM_A_CLK_OUT
uSD_Card: sd_hst0_clk, sd_hst0_cmd, sd_hst0_dat_0, sd_hst0_dat_1, sd_hst0_dat_2, sd_hst0_dat_3
MX_SPI0: SPI_SIO0, SPI_SIO1, SPI_CS_1, SPI_SCK, SPI_CS_2

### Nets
GND: B1.1 J2.1(GND) J2.2(GND) J2.7(GND) J2.8(GND) J2.13(GND) J2.14(GND) J2.19(GND) J2.20(GND) J2.25(GND) J2.26(GND) J2.30(GND) J2.31(GND) J2.43(RFU) J2.44(GND) J2.50(GND) J2.53(RFU) J2.58(RFU) J2.71(GND) J2.72(GND) J2.75(GND) J2.76(GND) J2.81(GND) J2.82(GND) J2.87(GND) J2.88(GND) J2.93(GND) J2.94(GND) J2.99(GND) J2.100(GND) R62.2 SW2.1 SW2.3 ; port GND
2485_PGOOD: J2.37(PGOOD) ; port 2485_PGOOD
2485_WAKEUP: J2.41(WAKEUP) R62.1 ; port 2485_WAKEUP
CAM_A_CLK_OUT: J2.28(IO44/CAM_A_CLK) ; port CTL_CAM_A.CAM_A_CLK_OUT
CAM_A_PWDN_N: J2.34(IO31/CAM_A_PWR) ; port CTL_CAM_A.CAM_A_PWDN_N
CAM_B_CLK_OUT: J2.73(IO47/CAM_B_CLK) ; port CTL_CAM_B.CAM_B_CLK_OUT
CAM_B_D_PWM: J2.65(IO57/CAM_L_PWR) ; port CTL_CAM_B.CAM_B_D_PWM
CAM_B_PWDN_N: J2.67(IO54/CAM_R_PWR) ; port CTL_CAM_B.CAM_B_PWDN_N
COM_AUX_IO2: R82.1 ; port COM_AUX_IO2
GPIO7/sd_hst_cd: J2.59(IO7/SD_CD) ; port GPIO7/sd_hst_cd
I2C1_SCL: J2.35(IO20/CAMA_I2C1_SCL) ; port I2C1.I2C1_SCL
I2C1_SDA: J2.33(IO21/CAMA_I2C1_SDA) ; port I2C1.I2C1_SDA
I2C2_SCL: J2.77(IO22/CAMB_I2C2_SCL) ; port I2C2.I2C2_SCL
I2C2_SDA: J2.79(IO23/CAMB_I2C2_SDA) ; port I2C2.I2C2_SDA
I2C3_SCL: J2.78(IO24/I2C3_SCL) ; port I2C3.I2C3_SCL
I2C3_SDA: J2.80(IO25/I2C3_SDA) ; port I2C3.I2C3_SDA
MIPI_RX2_C_N: J2.95(RX2_CAMB_CLKN) ; port MIPI_CAM_B.MIPI_RX2_C_N
MIPI_RX2_C_P: J2.97(RX2_CAMB_CLKP) ; port MIPI_CAM_B.MIPI_RX2_C_P
MIPI_RX2_D0_N: J2.89(RX2_CAMB_D0_N) ; port MIPI_CAM_B.MIPI_RX2_D0_N
MIPI_RX2_D0_P: J2.91(RX2_CAMB_D0_P) ; port MIPI_CAM_B.MIPI_RX2_D0_P
MIPI_RX2_D1_N: J2.83(RX2_CAMB_D1_N) ; port MIPI_CAM_B.MIPI_RX2_D1_N
MIPI_RX2_D1_P: J2.85(RX2_CAMB_D1_P) ; port MIPI_CAM_B.MIPI_RX2_D1_P
MIPI_RX3_C_N: J2.96(RX3_CAMC_CLKN) ; port MIPI_CAM_C.MIPI_RX3_C_N
MIPI_RX3_C_P: J2.98(RX3_CAMC_CLKP) ; port MIPI_CAM_C.MIPI_RX3_C_P
MIPI_RX3_D0_N: J2.90(RX3_CAMC_D0_N) ; port MIPI_CAM_C.MIPI_RX3_D0_N
MIPI_RX3_D0_P: J2.92(RX3_CAMC_D0_P) ; port MIPI_CAM_C.MIPI_RX3_D0_P
MIPI_RX3_D1_N: J2.84(RX3_CAMC_D1_N) ; port MIPI_CAM_C.MIPI_RX3_D1_N
MIPI_RX3_D1_P: J2.86(RX3_CAMC_D1_P) ; port MIPI_CAM_C.MIPI_RX3_D1_P
MIPI_RX4_C_N: J2.3(RX4_CAMA_CLKN) ; port MIPI_CAM_A.MIPI_RX4_C_N
MIPI_RX4_C_P: J2.5(RX4_CAMA_CLKP) ; port MIPI_CAM_A.MIPI_RX4_C_P
MIPI_RX4_D0_N: J2.9(RX4_CAMA_D0_N) ; port MIPI_CAM_A.MIPI_RX4_D0_N
MIPI_RX4_D0_P: J2.11(RX4_CAMA_D0_P) ; port MIPI_CAM_A.MIPI_RX4_D0_P
MIPI_RX4_D1_N: J2.15(RX4_CAMA_D1_N) ; port MIPI_CAM_A.MIPI_RX4_D1_N
MIPI_RX4_D1_P: J2.17(RX4_CAMA_D1_P) ; port MIPI_CAM_A.MIPI_RX4_D1_P
MIPI_RX5_D0_N: J2.21(RX5_CAMA_D2_N) ; port MIPI_CAM_A.MIPI_RX5_D0_N
MIPI_RX5_D0_P: J2.23(RX5_CAMA_D2_P) ; port MIPI_CAM_A.MIPI_RX5_D0_P
MIPI_RX5_D1_N: J2.27(RX5_CAMA_D3_N) ; port MIPI_CAM_A.MIPI_RX5_D1_N
MIPI_RX5_D1_P: J2.29(RX5_CAMA_D3_P) ; port MIPI_CAM_A.MIPI_RX5_D1_P
MODULE_nRST: B1.2 J2.39(_RST) ; port MODULE_nRST
sd_hst0_clk: J2.61(IO32_3V3/SD0_CLK) ; port uSD_Card.sd_hst0_clk
sd_hst0_cmd: J2.63(IO33_3V3/SD0_CMD) ; port uSD_Card.sd_hst0_cmd
sd_hst0_dat_0: J2.40(IO34_3V3/SD0_D0) ; port uSD_Card.sd_hst0_dat_0
sd_hst0_dat_1: J2.38(IO35_3V3/SD0_D1) ; port uSD_Card.sd_hst0_dat_1
sd_hst0_dat_2: J2.36(IO36_3V3/SD0_D2) ; port uSD_Card.sd_hst0_dat_2
sd_hst0_dat_3: J2.32(IO37_3V3/SD0_D3) ; port uSD_Card.sd_hst0_dat_3
SPI_BMI270_CS_1V8: J2.60(IO8/SPI0_SS_1) TP30.1 ; port MX_SPI0.SPI_CS_1
SPI_BNO085_CS_1V8: J2.70(IO5/SPI0_SS_0) ; port MX_SPI0.SPI_CS_2
SPI_MISO_1V8: J2.64(IO1/SPI0_SIO1) TP28.1 ; port MX_SPI0.SPI_SIO1
SPI_MOSI_1V8: J2.62(IO0/SPI0_SIO0) TP29.1 ; port MX_SPI0.SPI_SIO0
SPI_SCK_1V8: J2.74(IO4/SPI0_SCK) TP27.1 ; port MX_SPI0.SPI_SCK
SPI_SIO2: J2.66(IO2/SPI0_SIO2)
SPI_SIO3: J2.68(IO3/SPI0_SIO3)
NetJ2_47: J2.47(RFU) SW2.2 SW2.4
NetJ2_56: J2.56(RFU) R82.2

Not connected (* = marked no-connect by the designer): J2 4(CAMD_CLK_N) 6(CAMD_CLK_P) 10(CAMD_D0_N) 12(CAMD_D0_P) 16(CAMD_D1_N) 18(CAMD_D1_P) 22(CAMD_D2_N) 24(CAMD_D2_P) 42(IO41/AUX_IO2) 45(RFU) 46(CAMD_D3_N) 48(CAMD_D3_P) 49(RFU) 51(RFU) 52(RFU) 54(RFU) 55(RFU) 57(RFU) 69(IO53)

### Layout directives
differential pair; differential pair class 100ohm: MIPI_RX2_C_N, MIPI_RX2_C_P, MIPI_RX2_D0_N, MIPI_RX2_D0_P, MIPI_RX2_D1_N, MIPI_RX2_D1_P, MIPI_RX3_C_N, MIPI_RX3_C_P, MIPI_RX3_D0_N, MIPI_RX3_D0_P, MIPI_RX3_D1_N, MIPI_RX3_D1_P, MIPI_RX4_C_N, MIPI_RX4_C_P, MIPI_RX4_D0_N, MIPI_RX4_D0_P, MIPI_RX4_D1_N, MIPI_RX4_D1_P, MIPI_RX5_D0_N, MIPI_RX5_D0_P, MIPI_RX5_D1_N, MIPI_RX5_D1_P
net class MIPI_CAM_A: MIPI_RX4_C_N, MIPI_RX4_C_P, MIPI_RX4_D0_N, MIPI_RX4_D0_P, MIPI_RX4_D1_N, MIPI_RX4_D1_P, MIPI_RX5_D0_N, MIPI_RX5_D0_P, MIPI_RX5_D1_N, MIPI_RX5_D1_P
net class MIPI_CAM_C: MIPI_RX3_C_N, MIPI_RX3_C_P, MIPI_RX3_D0_N, MIPI_RX3_D0_P, MIPI_RX3_D1_N, MIPI_RX3_D1_P
net class MIPI_CAM_B: MIPI_RX2_C_N, MIPI_RX2_C_P, MIPI_RX2_D0_N, MIPI_RX2_D0_P, MIPI_RX2_D1_N, MIPI_RX2_D1_P
net class QSPI: SPI_BMI270_CS_1V8, SPI_BNO085_CS_1V8, SPI_MISO_1V8, SPI_MOSI_1V8, SPI_SCK_1V8, SPI_SIO2, SPI_SIO3
net class SDIO: sd_hst0_clk, sd_hst0_cmd, sd_hst0_dat_0, sd_hst0_dat_1, sd_hst0_dat_2, sd_hst0_dat_3

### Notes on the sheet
- IMU SPI is length matched between connector and IMU. QSPI bus is length matched between connector and header pads.

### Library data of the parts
B1 = DTSM-32N-V: SWITCH TACTILE SMT 3.5mm * 6mm , brown 160gf; Manufacturer 1: Diptronics; Manufacturer Part Number 1: DTSM-32N-V-T/R
J2 = CMP-005-000052-3: OAK-SoM-Pro base board conn. A; Manufacturer Part Number 1: DF40HC(3.0)-100DS-0.4V(58); Manufacturer 1: Hirose; Pitch: 0.016inch; Number of Positions: 100; System: Connector; Connector Type: Receptacle
R62 = RC0402FR-071KL: RES SMD 1K OHM 1% 1/16W 0402 1 kOhms ±1% 0.063W, 1/16W Chip Resistor 0402 (1005 Metric) Moisture Resistant Thick Film; Manufacturer 1: Yageo; Temperature Coefficient: 100ppm/°C; Power Rating: 62.5mW; Voltage Rating (DC): 50V; Resistance: 1kR
R82 = CMP-013-000022-2: as R44 on sheet CONNECTOR_B
SW2 = CMP-011-00016-3: as SW1 on sheet CONNECTOR_B
TP27-TP30 = TEST_POINT

## Sheet ETH_PCIE_PHY.SchDoc: =project_title
size Tabloid; CompanyName: Luxonis Holding; DrawnBy: Boris Chou / Blaz Kvas; Organization: Luxonis Holding; Address1: 1925 Harmony Park Drive; Address2: Westminster, CO; Address3: 80234; Address4: United States; DocumentNumber: D2088000; Revision: R1M1E1; SheetNumber: 7; SheetTotal: 12
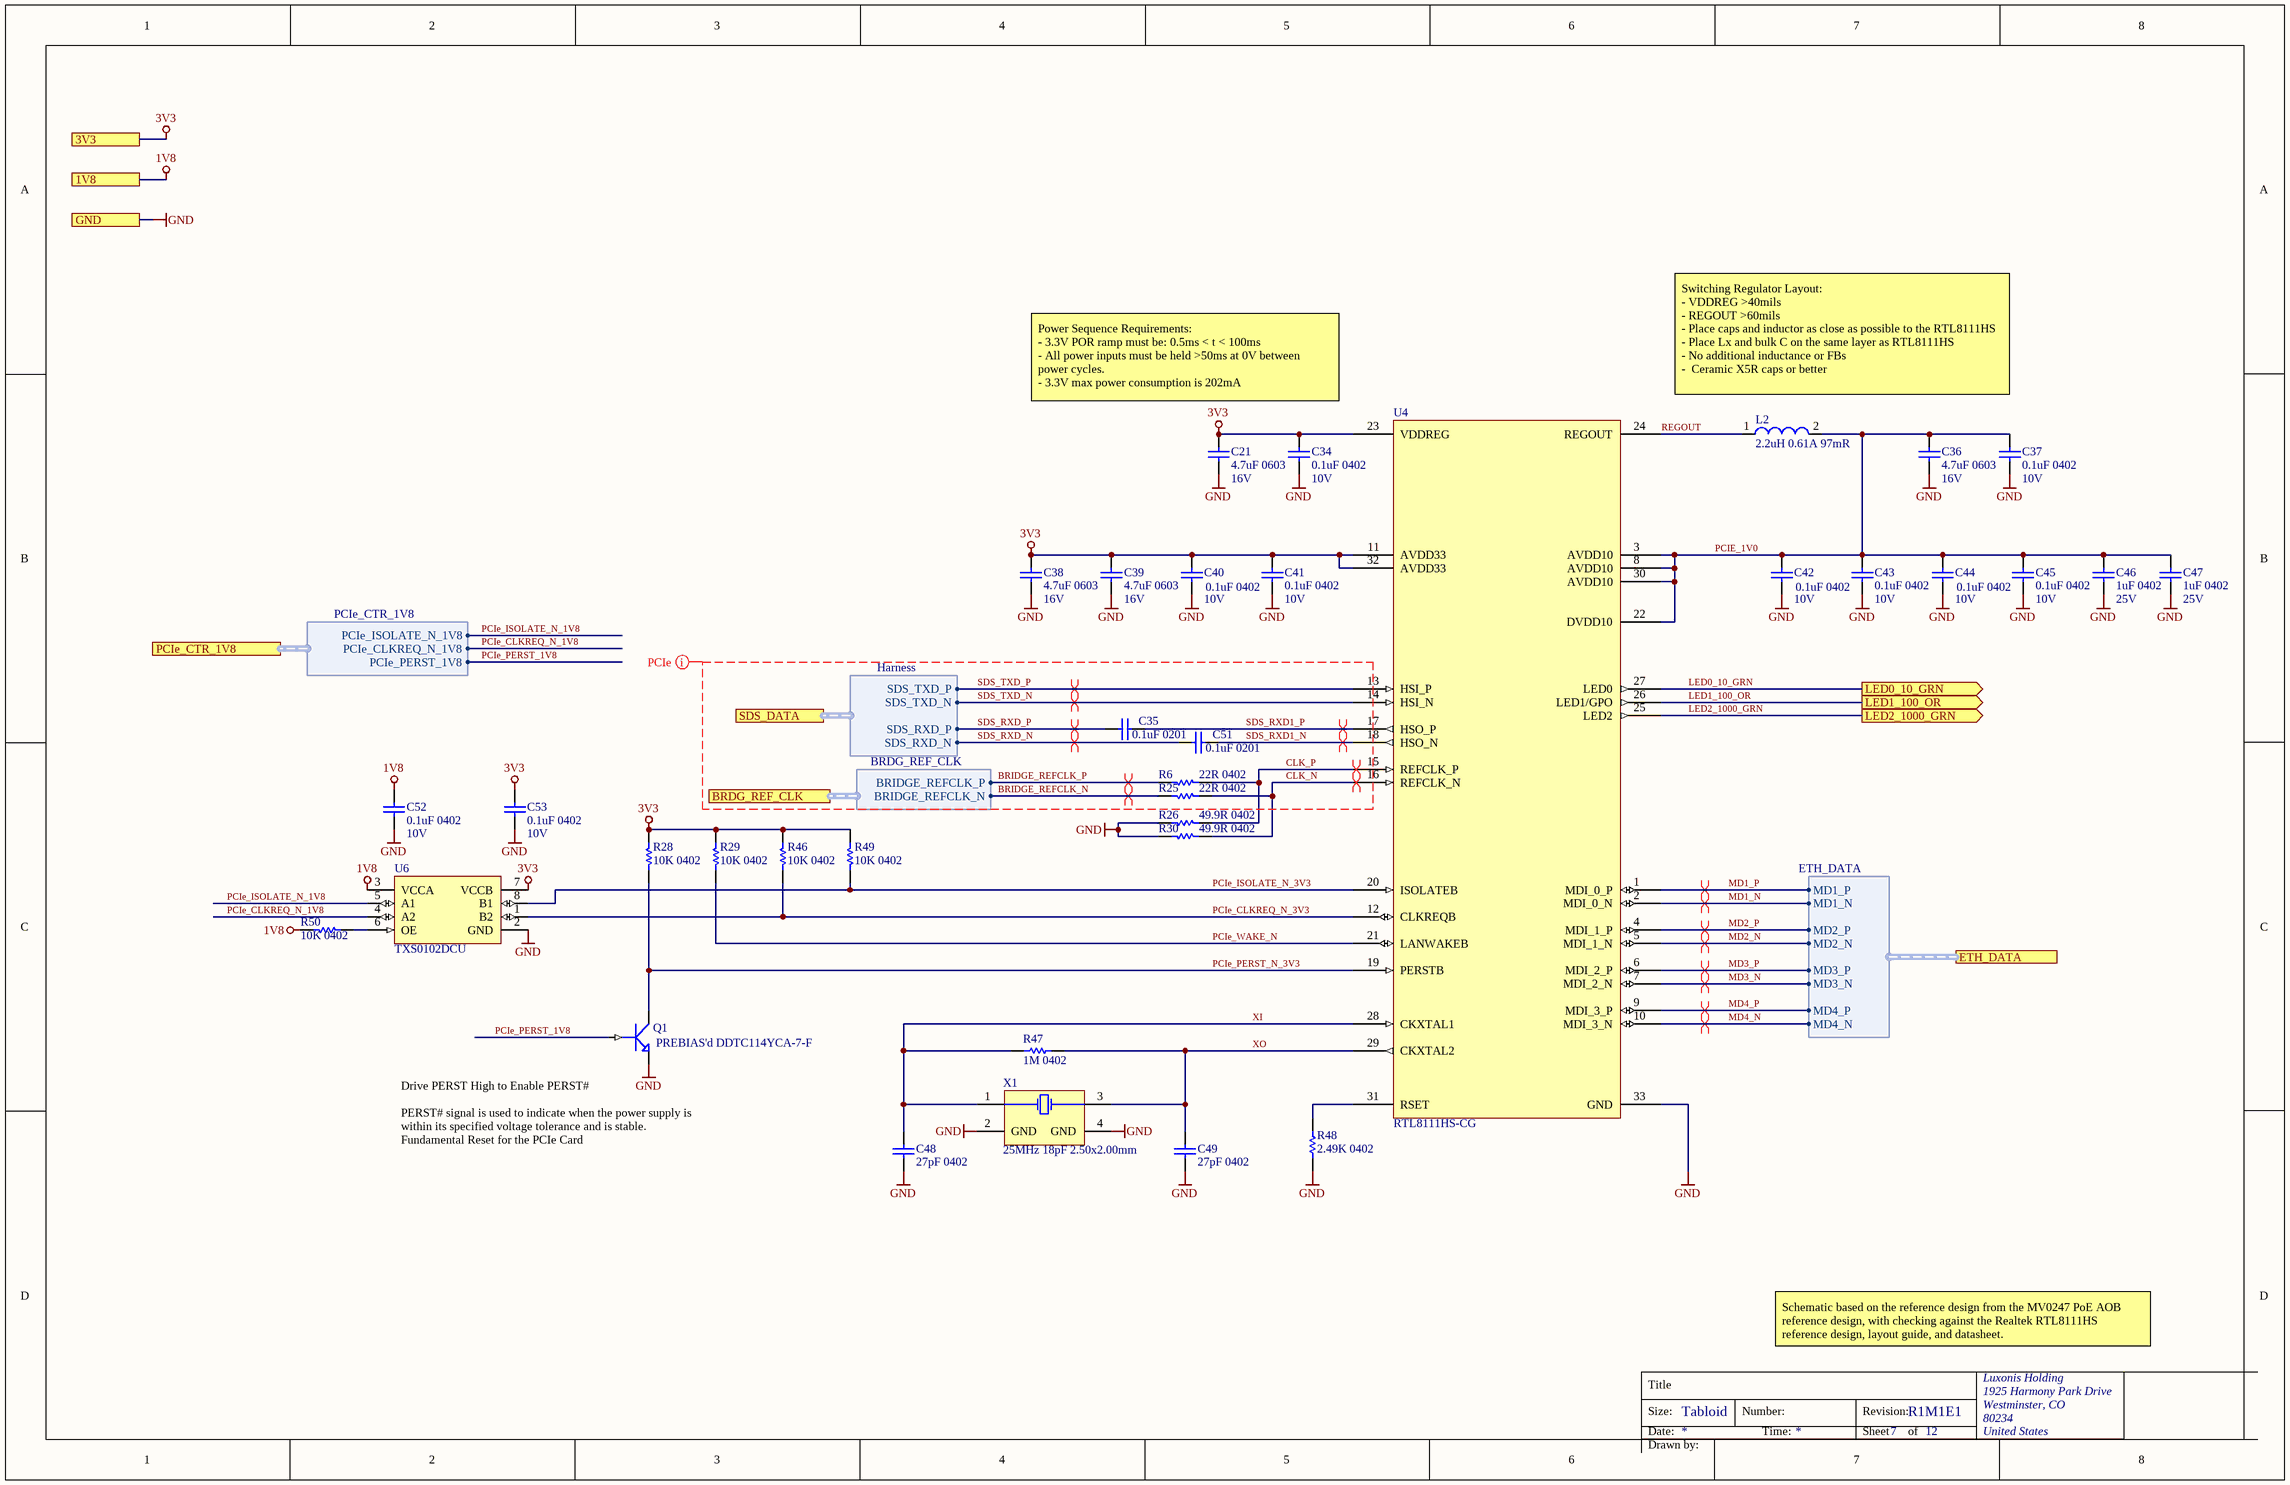
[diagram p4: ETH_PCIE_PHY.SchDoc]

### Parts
C21  4.7uF 0603  Voltage Rating: 16V  [CAPC0603(1608)100_N]
C34  0.1uF 0402  Voltage Rating: 10V  [CAPC0402(1005)70_N]
C35  0.1uF 0201  [CAPC0201(0603)33_L]
C36  4.7uF 0603  Voltage Rating: 16V  [CAPC0603(1608)100_N]
C37  0.1uF 0402  Voltage Rating: 10V  [CAPC0402(1005)70_N]
C38  4.7uF 0603  Voltage Rating: 16V  [CAPC0603(1608)100_N]
C39  4.7uF 0603  Voltage Rating: 16V  [CAPC0603(1608)100_N]
C40  0.1uF 0402  Voltage Rating: 10V  [CAPC0402(1005)70_N]
C41  0.1uF 0402  Voltage Rating: 10V  [CAPC0402(1005)70_N]
C42  0.1uF 0402  Voltage Rating: 10V  [CAPC0402(1005)70_N]
C43  0.1uF 0402  Voltage Rating: 10V  [CAPC0402(1005)70_N]
C44  0.1uF 0402  Voltage Rating: 10V  [CAPC0402(1005)70_N]
C45  0.1uF 0402  Voltage Rating: 10V  [CAPC0402(1005)70_N]
C46  1uF 0402  Voltage Rating: 25V  [CAPC0402(1005)70_N]
C47  1uF 0402  Voltage Rating: 25V  [CAPC0402(1005)70_N]
C48  27pF 0402  [CAPC0402(1005)60_N]
C49  27pF 0402  [CAPC0402(1005)60_N]
C51  0.1uF 0201  [CAPC0201(0603)33_L]
C52  0.1uF 0402  Voltage Rating: 10V  [CAPC0402(1005)70_N]
C53  0.1uF 0402  Voltage Rating: 10V  [CAPC0402(1005)70_N]
L2  2.2uH 0.61A 97mR  [LQH32NH2R2J23L]
Q1  PREBIAS'd DDTC114YCA-7-F  [DDTC114YCA-7-F]
R6  22R 0402  [RESC0402(1005)_L]
R25  22R 0402  [RESC0402(1005)_L]
R26  49.9R 0402  [RESC0402(1005)_L]
R28  10K 0402  [RESC0402(1005)_N]
R29  10K 0402  [RESC0402(1005)_N]
R30  49.9R 0402  [RESC0402(1005)_L]
R46  10K 0402  [RESC0402(1005)_N]
R47  1M 0402  [RESC0402(1005)_N]
R48  2.49K 0402  [RESC0402(1005)_N]
R49  10K 0402  [RESC0402(1005)_N]
R50  10K 0402  [RESC0402(1005)_N]
U4  RTL8111HS-CG  [RTL8111Hx-CG]
U6  TXS0102DCU  [TXS0102DCUR]
X1  25MHz 18pF 2.50x2.00mm  [ECS-250-18-36B-CKY-TR]

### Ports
1V8, 3V3, BRDG_REF_CLK (harness BRDG_REF_CLK), ETH_DATA (harness ETH_DATA), GND, LED0_10_GRN (out), LED1_100_OR (out), LED2_1000_GRN (out), PCIe_CTR_1V8 (harness PCIe_CTR_1V8), SDS_DATA (harness Harness)

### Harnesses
ETH_DATA: MD1_P, MD1_N, MD2_P, MD2_N, MD3_P, MD3_N, MD4_P, MD4_N
Harness: SDS_TXD_P, SDS_TXD_N, SDS_RXD_P, SDS_RXD_N
BRDG_REF_CLK: BRIDGE_REFCLK_P, BRIDGE_REFCLK_N
PCIe_CTR_1V8: PCIe_CLKREQ_N_1V8, PCIe_ISOLATE_N_1V8, PCIe_PERST_1V8

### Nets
1V8: C52.2 R50.2 U6.3(VCCA) ; port 1V8
3V3: C21.2 C34.2 C38.2 C39.2 C40.2 C41.2 C53.2 R28.1 R29.1 R46.1 R49.1 U4.11(AVDD33) U4.23(VDDREG) U4.32(AVDD33) U6.7(VCCB) ; port 3V3
GND: C21.1 C34.1 C36.1 C37.1 C38.1 C39.1 C40.1 C41.1 C42.1 C43.1 C44.1 C45.1 C46.1 C47.1 C48.1 C49.1 C52.1 C53.1 Q1.2(E) R26.1 R30.1 R48.1 U4.33(GND) U6.2(GND) X1.2(GND) X1.4(GND) ; port GND
BRIDGE_REFCLK_N: R25.2 ; port BRDG_REF_CLK.BRIDGE_REFCLK_N
BRIDGE_REFCLK_P: R6.2 ; port BRDG_REF_CLK.BRIDGE_REFCLK_P
CLK_N: R25.1 R30.2 U4.16(REFCLK_N)
CLK_P: R6.1 R26.2 U4.15(REFCLK_P)
LED0_10_GRN: U4.27(LED0) ; port LED0_10_GRN
LED1_100_OR: U4.26(LED1/GPO) ; port LED1_100_OR
LED2_1000_GRN: U4.25(LED2) ; port LED2_1000_GRN
MD1_N: U4.2(MDI_0_N) ; port ETH_DATA.MD1_N
MD1_P: U4.1(MDI_0_P) ; port ETH_DATA.MD1_P
MD2_N: U4.5(MDI_1_N) ; port ETH_DATA.MD2_N
MD2_P: U4.4(MDI_1_P) ; port ETH_DATA.MD2_P
MD3_N: U4.7(MDI_2_N) ; port ETH_DATA.MD3_N
MD3_P: U4.6(MDI_2_P) ; port ETH_DATA.MD3_P
MD4_N: U4.10(MDI_3_N) ; port ETH_DATA.MD4_N
MD4_P: U4.9(MDI_3_P) ; port ETH_DATA.MD4_P
PCIE_1V0: C36.2 C37.2 C42.2 C43.2 C44.2 C45.2 C46.2 C47.2 L2.2 U4.3(AVDD10) U4.8(AVDD10) U4.22(DVDD10) U4.30(AVDD10)
PCIe_CLKREQ_N_1V8: U6.4(A2) ; port PCIe_CTR_1V8.PCIe_CLKREQ_N_1V8
PCIe_CLKREQ_N_3V3: R46.2 U4.12(CLKREQB) U6.1(B2)
PCIe_ISOLATE_N_1V8: U6.5(A1) ; port PCIe_CTR_1V8.PCIe_ISOLATE_N_1V8
PCIe_ISOLATE_N_3V3: R49.2 U4.20(ISOLATEB) U6.8(B1)
PCIe_PERST_1V8: Q1.1(B) ; port PCIe_CTR_1V8.PCIe_PERST_1V8
PCIe_PERST_N_3V3: Q1.3(C) R28.2 U4.19(PERSTB)
PCIe_WAKE_N: R29.2 U4.21(LANWAKEB)
REGOUT: L2.1 U4.24(REGOUT)
SDS_RXD1_N: C51.2 U4.18(HSO_N)
SDS_RXD1_P: C35.2 U4.17(HSO_P)
SDS_RXD_N: C51.1 ; port SDS_DATA.SDS_RXD_N
SDS_RXD_P: C35.1 ; port SDS_DATA.SDS_RXD_P
SDS_TXD_N: U4.14(HSI_N) ; port SDS_DATA.SDS_TXD_N
SDS_TXD_P: U4.13(HSI_P) ; port SDS_DATA.SDS_TXD_P
XI: C48.2 R47.1 U4.28(CKXTAL1) X1.1(X1)
XO: C49.2 R47.2 U4.29(CKXTAL2) X1.3(X2)
NetR48_2: R48.2 U4.31(RSET)
NetR50_1: R50.1 U6.6(OE)

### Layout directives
differential pair; net class ETH; differential pair class 100ohm: MD1_N, MD1_P, MD2_N, MD2_P, MD3_N, MD3_P, MD4_N, MD4_P
differential pair; differential pair class 100ohm: BRIDGE_REFCLK_N, BRIDGE_REFCLK_P, CLK_N, CLK_P, SDS_RXD1_N, SDS_RXD1_P, SDS_RXD_N, SDS_RXD_P, SDS_TXD_N, SDS_TXD_P
net class PCIe: BRIDGE_REFCLK_N, BRIDGE_REFCLK_P, CLK_N, CLK_P, SDS_RXD1_N, SDS_RXD1_P, SDS_RXD_N, SDS_RXD_P, SDS_TXD_N, SDS_TXD_P

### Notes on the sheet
- Power Sequence Requirements:
  - 3.3V POR ramp must be: 0.5ms < t < 100ms
  - All power inputs must be held >50ms at 0V between power cycles.
  - 3.3V max power consumption is 202mA
- Switching Regulator Layout:
  - VDDREG >40mils
  - REGOUT >60mils
  - Place caps and inductor as close as possible to the RTL8111HS
  - Place Lx and bulk C on the same layer as RTL8111HS
  - No additional inductance or FBs
  -  Ceramic X5R caps or better
- (near Q1) Drive PERST High to Enable PERST#
- PERST# signal is used to indicate when the power supply is within its specified voltage tolerance and is stable.
  Fundamental Reset for the PCIe Card
- Schematic based on the reference design from the MV0247 PoE AOB reference design, with checking against the Realtek RTL8111HS reference design, layout guide, and datasheet.

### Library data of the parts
C21 C36 C38 C39 = GRM188R61C475KAAJD: CAP CER 4.7UF 16V X5R 0603 10%; Manufacturer 1: Murata; Material: Ceramic
C34 C37 C40-C45 C52 C53 = GRM155R71A104JA01D: CAP CER 0.1UF 10V X7R 0402 5%; Manufacturer 1: Murata; Capacitance: 100nF
C35 C51 = GRM033R61A104KE15D: CAP CER 0.1UF 10V X5R 0201; Manufacturer 1: Murata; Capacitance: 100nF; Tolerance: 10%
C46 C47 = GRM155R61E105KA12D: CAP CER 1UF 25V X5R 0402 10%; Manufacturer 1: Murata; Material: Ceramic
C48 C49 = C0402C270J5GACTU: CAP CER 27PF 50V C0G/NP0 0402; Manufacturer 1: KEMET; Dielectric Material: Ceramic; Tolerance: 5%; Dielectric: C0G; Temperature Coefficient: 30ppm/°C
L2 = LQH32NH2R2J23L: FIXED IND 2.2UH 610MA 97MOHM SMD; Manufacturer 1: Murata; Core Material: Ferrite; Tolerance: 5%; Shielding: Unshielded; Self Resonant Frequency: 75MHz; Test Frequency: 1MHz
Q1 = DDTC114YCA-7-F: TRANS PREBIAS NPN 200MW SOT23-3; Manufacturer 1: Diodes; Element Configuration: Single; Collector Emitter Voltage (VCEO): 50V; Current Rating: 100mA; hFE Min: 68; Transition Frequency: 250MHz
R6 R25 = RC0402FR-0722RL: RES SMD 22 OHM 1% 1/16W 0402; Manufacturer 1: Yageo; Temperature Coefficient: 100ppm/°C; Power Rating: 63mW; Voltage Rating: 50V
R26 R30 = RC0402FR-0749R9L: RES SMD 49.9 OHM 1% 1/16W 0402; Manufacturer 1: Yageo; Power Rating: 62.5mW; Temperature Coefficient: 100ppm/°C; Voltage Rating: 50V; Max Power Dissipation: 63mW
R28 R29 R46 R49 R50 = RC0402FR-1310KL: as R79 on sheet CONNECTOR_B
R47 = RC0402FR-071ML: RES SMD 1M OHM 1% 1/16W 0402; Manufacturer 1: Yageo; Resistance: 1MR; Temperature Coefficient: 100ppm/°C; Power Rating: 63mW; Voltage Rating: 50V
R48 = RC0402FR-072K49L: RES SMD 2.49K OHM 1% 1/16W 0402; Manufacturer 1: Yageo; Resistance: 2.49kR; Temperature Coefficient: 100ppm/°C; Power Rating: 62.5mW; Voltage Rating: 50V; Max Power Dissipation: 63mW
U4 = RTL8111HS: IC ETHERNET/PCIe PHY Realtek
U6 = TXS0102DCUR: TEXAS INSTRUMENTS - TXS0102DCUR - IC, TRANSLATOR, 2 BIT, BI, US-8; Min Supply Voltage: 1.65V; Max Supply Voltage: 5.5V; Data Rate: 24Mbps; Number of Channels: 2; Propagation Delay: 4.6ns; Turn-On Delay Time: 260ns; High Level Output Current: -20uA; Low Level Output Current: 1mA; Quiescent Current: 14.4uA; Output Type: Voltage; Output Current: 1A
X1 = ECS-250-18-36B-CKY-TR: CRYSTAL 25.0000MHZ 18PF SMD 25MHz ±10ppm Crystal 18pF 50 Ohms 4-SMD, No Lead; Manufacturer 1: ECS International

## Sheet RJ45.SchDoc: =project_title
size Tabloid; CompanyName: Luxonis Holding; DrawnBy: Boris Chou / Blaz Kvas; Organization: Luxonis Holding; Address1: 1925 Harmony Park Drive; Address2: Westminster, CO; Address3: 80234; Address4: United States; DocumentNumber: D2088000; Revision: R1M1E1; SheetNumber: 8; SheetTotal: 12
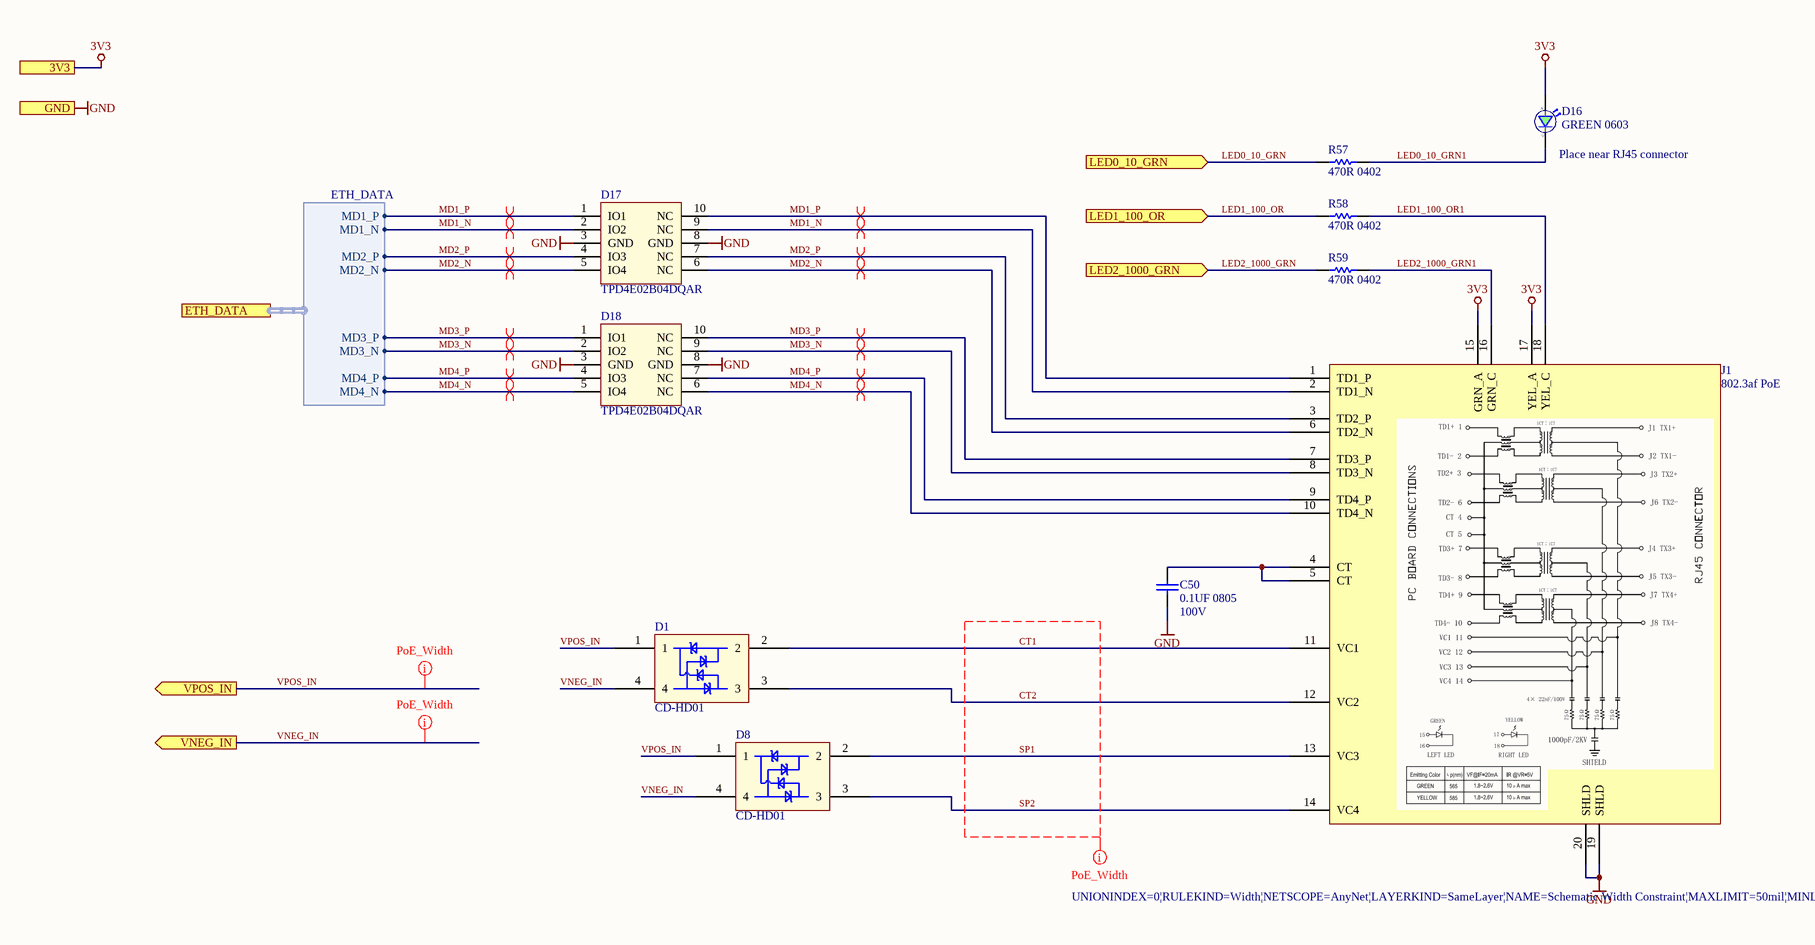
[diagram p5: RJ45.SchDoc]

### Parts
C50  0.1UF 0805  Voltage Rating: 100V  [CAPC0805(2012)145_N]
D1  CD-HD01  [CD-H01]
D8  CD-HD01  [CD-H01]
D16  GREEN 0603  [SML_D1xx8W]
D17  TPD4E02B04DQAR  [TPD4E02B04DQAR]
D18  TPD4E02B04DQAR  [TPD4E02B04DQAR]
J1  802.3af PoE  [TRJG0926HENL]
R57  470R 0402  [RESC0402(1005)_N]
R58  470R 0402  [RESC0402(1005)_N]
R59  470R 0402  [RESC0402(1005)_N]

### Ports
3V3, ETH_DATA (harness ETH_DATA), GND, LED0_10_GRN (in), LED1_100_OR (in), LED2_1000_GRN (in), VNEG_IN (out), VPOS_IN (out)

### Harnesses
ETH_DATA: MD1_P, MD1_N, MD2_P, MD2_N, MD3_P, MD3_N, MD4_P, MD4_N

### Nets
3V3: D16.2(A) J1.15(GRN_A) J1.17(YEL_A) ; port 3V3
GND: C50.1 D17.3(GND) D17.8(GND) D18.3(GND) D18.8(GND) J1.19(SHLD) J1.20(SHLD) ; port GND
VNEG_IN: D1.4 D8.4 ; port VNEG_IN
CT1: D1.2 J1.11(VC1)
CT2: D1.3 J1.12(VC2)
LED0_10_GRN: R57.1 ; port LED0_10_GRN
LED0_10_GRN1: D16.1(C) R57.2
LED1_100_OR: R58.1 ; port LED1_100_OR
LED1_100_OR1: J1.18(YEL_C) R58.2
LED2_1000_GRN: R59.1 ; port LED2_1000_GRN
LED2_1000_GRN1: J1.16(GRN_C) R59.2
MD1_N: D17.2(IO2) D17.9(NC) J1.2(TD1_N) ; port ETH_DATA.MD1_N
MD1_P: D17.1(IO1) D17.10(NC) J1.1(TD1_P) ; port ETH_DATA.MD1_P
MD2_N: D17.5(IO4) D17.6(NC) J1.6(TD2_N) ; port ETH_DATA.MD2_N
MD2_P: D17.4(IO3) D17.7(NC) J1.3(TD2_P) ; port ETH_DATA.MD2_P
MD3_N: D18.2(IO2) D18.9(NC) J1.8(TD3_N) ; port ETH_DATA.MD3_N
MD3_P: D18.1(IO1) D18.10(NC) J1.7(TD3_P) ; port ETH_DATA.MD3_P
MD4_N: D18.5(IO4) D18.6(NC) J1.10(TD4_N) ; port ETH_DATA.MD4_N
MD4_P: D18.4(IO3) D18.7(NC) J1.9(TD4_P) ; port ETH_DATA.MD4_P
SP1: D8.2 J1.13(VC3)
SP2: D8.3 J1.14(VC4)
VPOS_IN: D1.1 D8.1 ; port VPOS_IN
NetC50_2: C50.2 J1.4(CT) J1.5(CT)

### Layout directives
differential pair; net class ETH; differential pair class 100ohm: MD1_N, MD1_P, MD2_N, MD2_P, MD3_N, MD3_P, MD4_N, MD4_P
rule Width Constraint [Pref Width = 15mil    Min Width = 4mil    Max Width = 50mil]; net class PoE: CT1, CT2, SP1, SP2, VNEG_IN, VPOS_IN

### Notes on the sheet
- (near D16) Place near RJ45 connector

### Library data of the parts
C50 = CL21B104KCFNNNE: CAP CER 0.1UF 100V X7R 0805; Manufacturer 1: Samsung; Tolerance: 10%; Capacitance: 100nF
D1 D8 = CD-HD01: CD-HD0x Series Schottky Bridge Rectifier Diode 100V 4-Pin Surface Mount T/R; Manufacturer 1: Bourns; Average Rectified Current: 1A
D16 = SML-D12M8WT86: LED GREEN DIFFUSED 0603 SMD Green 572nm LED Indication - Discrete 2.2V 0603 (1608 Metric); Manufacturer: Rohm; Colour: Green,Yellow; Lens Colour: White,Clear,Diffused; Lens Style: Diffused,Colorless,Rectangular; Forward Current: 20mA; Luminous Intensity: 25mcd; Number of LEDs: 1; Viewing Angle: 160°; Lens Color: White,Diffused
D17 D18 = TPD4E02B04DQAR: TVS DIODE 3.6V 8.8V 10USON 8.8V (Typ) Clamp 5A (8/20µs) Ipp Tvs Diode Surface Mount 10-USON (2.5x1); Manufacturer 1: Texas Instruments; Number of Bidirectional Channels: 4; Min Breakdown Voltage: 5.5V; Peak Pulse Power: 17W; Power Line Protection: No; Interface: USB,HDMI
J1 = TRJG0926HENL: CONN MAGJACK 1PORT 1000 BASET; Manufacturer 1: Trxcom; System: Connector
R57-R59 = CRCW0402470RFKED: RES SMD 470 OHM 1% 1/16W 0402; Manufacturer 1: Vishay; Temperature Coefficient: 100ppm/°C; Power Rating: 63mW; Voltage Rating: 50V

## Sheet USB.SchDoc: =project_title
size Tabloid; PageSetup: Record=PageOptions¦CenterHorizontal=True¦CenterVertical=True¦PrintScale=0.73¦XCorrection=1.00¦YCorrection=1.00¦PrintKind=0¦BorderSize=5000000¦LeftOffset=0¦BottomOffset=0¦Orientation=2¦PaperLength=1000¦PaperWidth=1000¦Scale=100¦PaperSource=7¦PrintQuality=-4¦MediaType=1¦DitherType=10¦PaperKind=A4¦PrintScaleMode=1; CompanyName: Luxonis Holding; DrawnBy: Boris Chou / Blaz Kvas; Organization: Luxonis Holding; Address1: 1925 Harmony Park Drive; Address2: Westminster, CO; Address3: 80234; Address4: United States; DocumentNumber: D2088000; Revision: R1M1E1; SheetNumber: 11; SheetTotal: 12
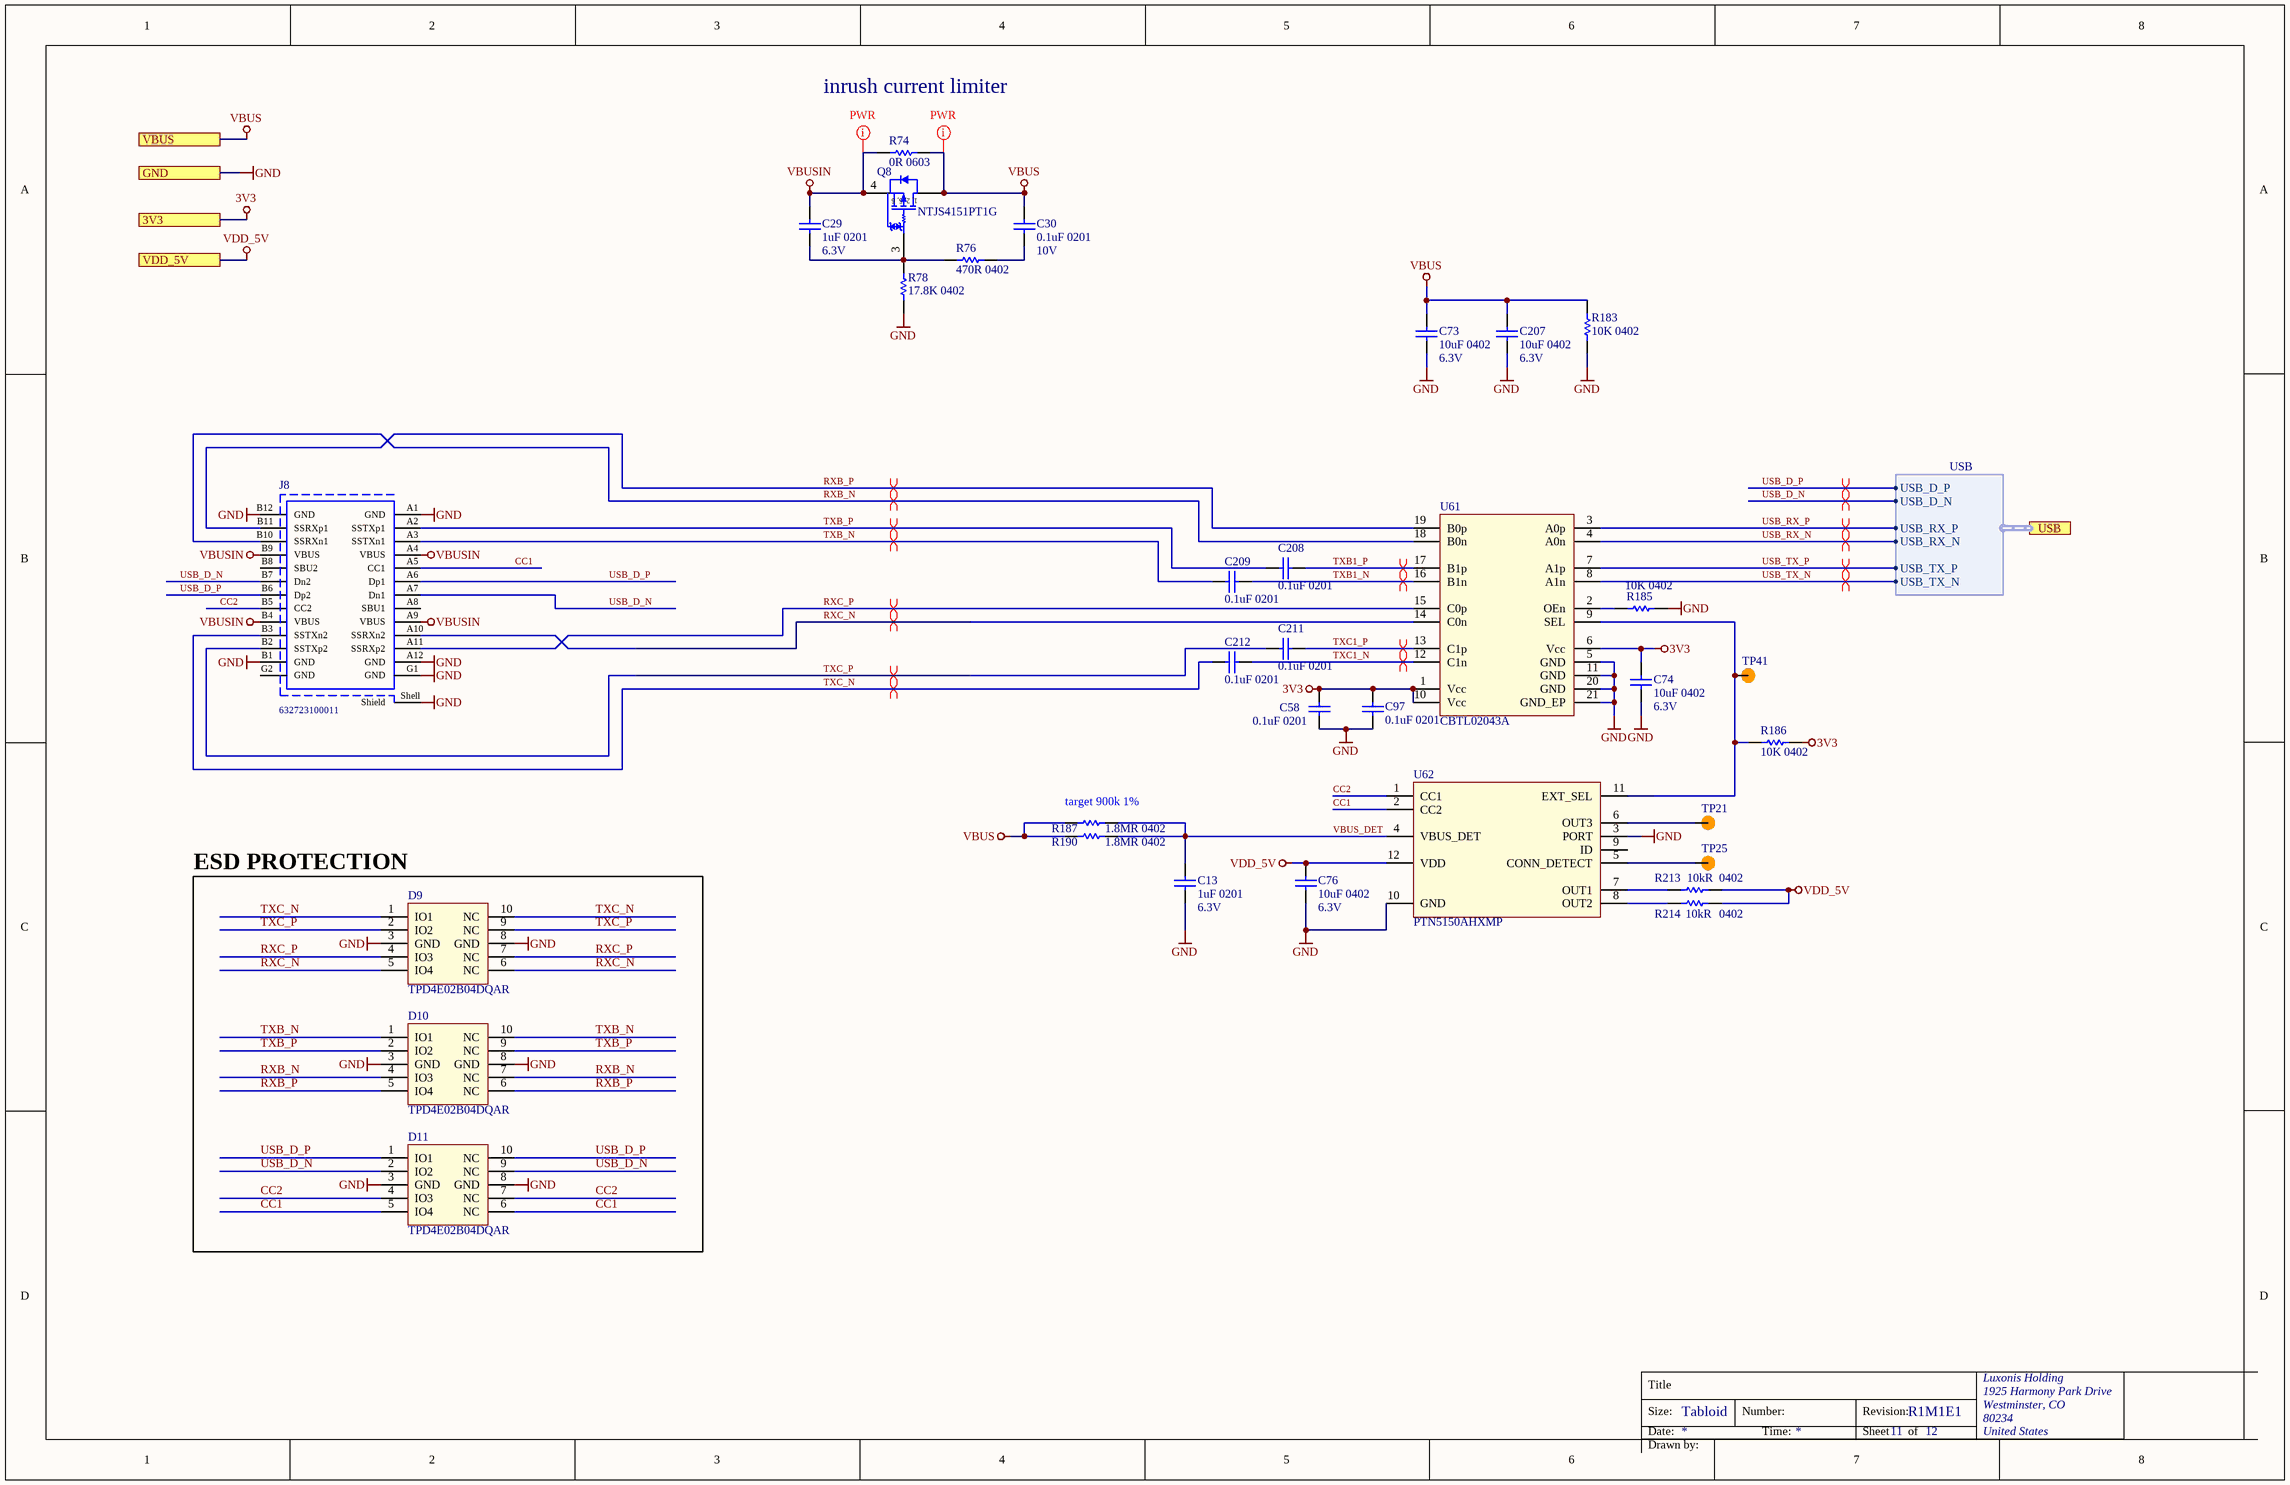
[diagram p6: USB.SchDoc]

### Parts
C13  1uF 0201  Voltage: 6.3V  [CAPC0201(0603)33_L]
C29  1uF 0201  Voltage: 6.3V  [CAPC0201(0603)33_L]
C30  0.1uF 0201  Voltage: 10V  [CAPC0201(0603)33_L]
C58  0.1uF 0201  [CAPC0201(0603)33_L]
C73  10uF 0402  Voltage Rating: 6.3V  [CAPC0402(1005)70_N]
C74  10uF 0402  Voltage Rating: 6.3V  [CAPC0402(1005)70_N]
C76  10uF 0402  Voltage Rating: 6.3V  [CAPC0402(1005)70_L]
C97  0.1uF 0201  [CAPC0201(0603)33_L]
C207  10uF 0402  Voltage Rating: 6.3V  [CAPC0402(1005)70_N]
C208  0.1uF 0201  [CAPC0201(0603)33_L]
C209  0.1uF 0201  [CAPC0201(0603)33_L]
C211  0.1uF 0201  [CAPC0201(0603)33_L]
C212  0.1uF 0201  [CAPC0201(0603)33_L]
D9  TPD4E02B04DQAR  [TPD4E02B04DQAR]
D10  TPD4E02B04DQAR  [TPD4E02B04DQAR]
D11  TPD4E02B04DQAR  [TPD4E02B04DQAR]
J8  632723100011  [632723100011]
Q8  NTJS4151PT1G  [ONSC-SC70-6-419B-02_W_V]
R74  0R 0603  [RESC0603(1608)_L]
R76  470R 0402  [RESC0402(1005)_L]
R78  17.8K 0402  [RESC0402(1005)_L]
R183  10K 0402  [RESC0402(1005)_N]
R185  10K 0402  [RESC0402(1005)_N]
R186  10K 0402  [RESC0402(1005)_N]
R187  1.8MR 0402  [RESC0402(1005)_N]
R190  1.8MR 0402  [RESC0402(1005)_N]
R213  Resistance: 10kR  Case/Package: 0402  [RESC0402(1005)_N]  (hidden comment: RC0402FR-1310KL)
R214  Resistance: 10kR  Case/Package: 0402  [RESC0402(1005)_N]  (hidden comment: RC0402FR-1310KL)
TP21  TEST_POINT  [TP075_150_NS]  (value not drawn)  (no BOM)
TP25  TEST_POINT  [TP075_150_NS]  (value not drawn)  (no BOM)
TP41  TEST_POINT  [TP075_150_NS]  (value not drawn)  (no BOM)
U61  CBTL02043A  [CBTL02043A]
U62  PTN5150AHXMP  [PTN5150H]

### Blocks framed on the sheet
ESD PROTECTION: D9-D11

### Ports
3V3, GND, USB (harness USB), VBUS, VDD_5V

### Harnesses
USB: USB_D_P, USB_D_N, USB_TX_N, USB_TX_P, USB_RX_N, USB_RX_P

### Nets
3V3: C58.2 C74.2 C97.2 R186.2 U61.1(Vcc) U61.6(Vcc) U61.10(Vcc) ; port 3V3
GND: C13.1 C58.1 C73.1 C74.1 C76.1 C97.1 C207.1 D9.3(GND) D9.8(GND) D10.3(GND) D10.8(GND) D11.3(GND) D11.8(GND) J8.A1(GND) J8.A12(GND) J8.B1(GND) J8.B12(GND) J8.G1(GND) J8.Shell(Shield) R78.1 R183.1 R185.2 U61.5(GND) U61.11(GND) U61.20(GND) U61.21(GND_EP) U62.3(PORT) U62.10(GND) ; port GND
VBUS: C30.2 C73.2 C207.2 Q8.1(D) Q8.2(D) Q8.5(D) Q8.6(D) R74.2 R183.2 R187.1 R190.1 ; port VBUS
VBUSIN: C29.2 J8.A4(VBUS) J8.A9(VBUS) J8.B4(VBUS) J8.B9(VBUS) Q8.4(S) R74.1
VDD_5V: C76.2 R213.2 R214.2 U62.12(VDD) ; port VDD_5V
CC1: D11.5(IO4) D11.6(NC) J8.A5(CC1) U62.2(CC2)
CC2: D11.4(IO3) D11.7(NC) J8.B5(CC2) U62.1(CC1)
RXB_N: D10.4(IO3) D10.7(NC) J8.B10(SSRXn1) U61.18(B0n)
RXB_P: D10.5(IO4) D10.6(NC) J8.B11(SSRXp1) U61.19(B0p)
RXC_N: D9.5(IO4) D9.6(NC) J8.A10(SSRXn2) U61.14(C0n)
RXC_P: D9.4(IO3) D9.7(NC) J8.A11(SSRXp2) U61.15(C0p)
TXB1_N: C209.2 U61.16(B1n)
TXB1_P: C208.2 U61.17(B1p)
TXB_N: C209.1 D10.1(IO1) D10.10(NC) J8.A3(SSTXn1)
TXB_P: C208.1 D10.2(IO2) D10.9(NC) J8.A2(SSTXp1)
TXC1_N: C212.2 U61.12(C1n)
TXC1_P: C211.2 U61.13(C1p)
TXC_N: C212.1 D9.1(IO1) D9.10(NC) J8.B3(SSTXn2)
TXC_P: C211.1 D9.2(IO2) D9.9(NC) J8.B2(SSTXp2)
USB_D_N: D11.2(IO2) D11.9(NC) J8.A7(Dn1) J8.B7(Dn2) ; port USB.USB_D_N
USB_D_P: D11.1(IO1) D11.10(NC) J8.A6(Dp1) J8.B6(Dp2) ; port USB.USB_D_P
USB_RX_N: U61.4(A0n) ; port USB.USB_RX_N
USB_RX_P: U61.3(A0p) ; port USB.USB_RX_P
USB_TX_N: U61.8(A1n) ; port USB.USB_TX_N
USB_TX_P: U61.7(A1p) ; port USB.USB_TX_P
VBUS_DET: C13.2 R187.2 R190.2 U62.4(VBUS_DET)
NetC29_1: C29.1 Q8.3(G) R76.1 R78.2
NetC30_1: C30.1 R76.2
NetR185_1: R185.1 U61.2(OEn)
NetR186_1: R186.1 TP41.1 U61.9(SEL) U62.11(EXT_SEL)
NetR213_1: R213.1 U62.7(OUT1)
NetR214_1: R214.1 U62.8(OUT2)
NetTP21_1: TP21.1 U62.6(OUT3)
NetTP25_1: TP25.1 U62.5(CONN_DETECT)

Not connected (* = marked no-connect by the designer): J8 A8(SBU1) B8(SBU2) G2(GND); U62 9(ID)

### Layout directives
differential pair; differential pair class USB3: RXB_N, RXB_P, RXC_N, RXC_P, TXB1_N, TXB1_P, TXB_N, TXB_P, TXC1_N, TXC1_P, TXC_N, TXC_P, USB_D_N, USB_D_P, USB_RX_N, USB_RX_P, USB_TX_N, USB_TX_P
net class Power_trace: VBUS, VBUSIN

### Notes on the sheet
- inrush current limiter
- (near R187) target 900k 1%

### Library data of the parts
C13 C29 = GRM033R60J105MEA2D: CAP CER 1UF 6.3V X5R 0201 20%; Manufacturer 1: Murata
C30 C58 C97 C208 C209 C211 C212 = GRM033R61A104KE15D: as C35 on sheet ETH_PCIE_PHY
C73 C74 C76 C207 = GRM155R60J106ME15D: CAP CER 10UF 6.3V X5R 0402 20%; Manufacturer 1: Murata
D9-D11 = CMP-111-000006-1: TVS DIODE 3.6V 8.8V 10USON 8.8V (Typ) Clamp 5A (8/20µs) Ipp Tvs Diode Surface Mount 10-USON (2.5x1); Manufacturer 1: Texas Instruments; Number of Bidirectional Channels: 4; Min Breakdown Voltage: 5.5V; Peak Pulse Power: 17W; Power Line Protection: No; Interface: USB,HDMI
J8 = CMP-002-00096-1: USB C 3.1 Connector, 24 Contact(s), Female, Right Angle, Solder and Surface Mount Terminal, Receptacle; Manufacturer 1: Wurth Electronics; Connector Type: TELECOM AND DATACOM CONNECTOR
Q8 = NTJS4151PT1G: Trench Power MOSFET, -20 V, -4.2 A, Single P-Channel, 6-Pin SC70, Pb-Free, Tape and Reel; Manufacturer 1: ON Semiconductor; VGS(th) Max (V): 1.2; VGS Max (V): 12; Crss Typ (pF): 110; Ciss Typ (pF): 850; PD Max (W): 1; Qrr Typ (nC): 0.23; ID Max (A): 4.2; Coss Typ (pF): 160; Channel Polarity: P Channel; V(BR)DSS Min (V): 20
R74 = CRCW06030000Z0EA: RES SMD 0 OHM JUMPER 1/10W 0603 0 Ohms Jumper 0.1W, 1/10W Chip Resistor 0603 (1608 Metric) Automotive AEC-Q200 Thick Film; Manufacturer 1: Vishay; Manufacturer Part Number 1: CRCW0603-0000Z0EA; Resistance: 0mR; Power Rating: 100mW; Voltage Rating: 75V; Temperature Coefficient: 100ppm/°C; Tolerance: 5%; Current Rating: 2A
R76 = CRCW0402470RFKED: as R57 on sheet RJ45
R78 = ERJ-2RKF1782X: RES SMD 17.8K OHM 1% 1/10W 0402 17.8 kOhms ±1% 0.1W, 1/10W Chip Resistor 0402 (1005 Metric) Automotive AEC-Q200 Thick Film; Manufacturer 1: Panasonic; Temperature Coefficient: 100ppm/°C; Power Rating: 100mW; Voltage Rating: 50V; Resistance: 17.8kR
R183 R185 R186 = RC0402FR-1310KL: as R79 on sheet CONNECTOR_B
R187 R190 = CRCW04021M80FKED: RES SMD 1.8M OHM 1% 1/16W 0402; Manufacturer 1: Vishay; Voltage Rating: 50V; Temperature Coefficient: 100ppm/°C; Power Rating: 63mW
R213 R214 = CMP-115-000004-1: RES SMD 10K OHM 1% 0402 1/16W Chip Resistor, 0402 [1005 Metric], 10 kohm, RC Series, 50 V, Thick Film, 62.5 mW; Manufacturer 1: Yageo; Working Voltage: 50V; Power Rating: 62.5mW; Temperature Coefficient: 100ppm/°C
TP21 TP25 TP41 = CMP-015-000000-1
U61 = CMP-045-000000-1: Multiplexer And Demux/Decoder, CBT/FST/QS/5C/B Series, 1-Func, 2 Line Input, 1 Line Output, True Output, PQCC20; Manufacturer Part Number 1: CBTL02043ABQ,115; Manufacturer 1: NXP Semiconductors
U62 = CMP-044-000000-2: Power Supply Support Circuit, Fixed, 2 Channel, 0.2, PQCC12; Manufacturer Part Number 1: PTN5150HXMP; Manufacturer 1: NXP Semiconductors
